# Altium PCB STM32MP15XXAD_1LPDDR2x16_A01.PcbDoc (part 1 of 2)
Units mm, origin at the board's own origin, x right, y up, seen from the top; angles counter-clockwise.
Board outline 86 x 120 mm, 4 copper layers (Top Layer, Signal Layer 1, Signal Layer 2, Bottom Layer), stack 1.571 mm thick; 88 components, 79 nets, 759 pads, 355 vias.
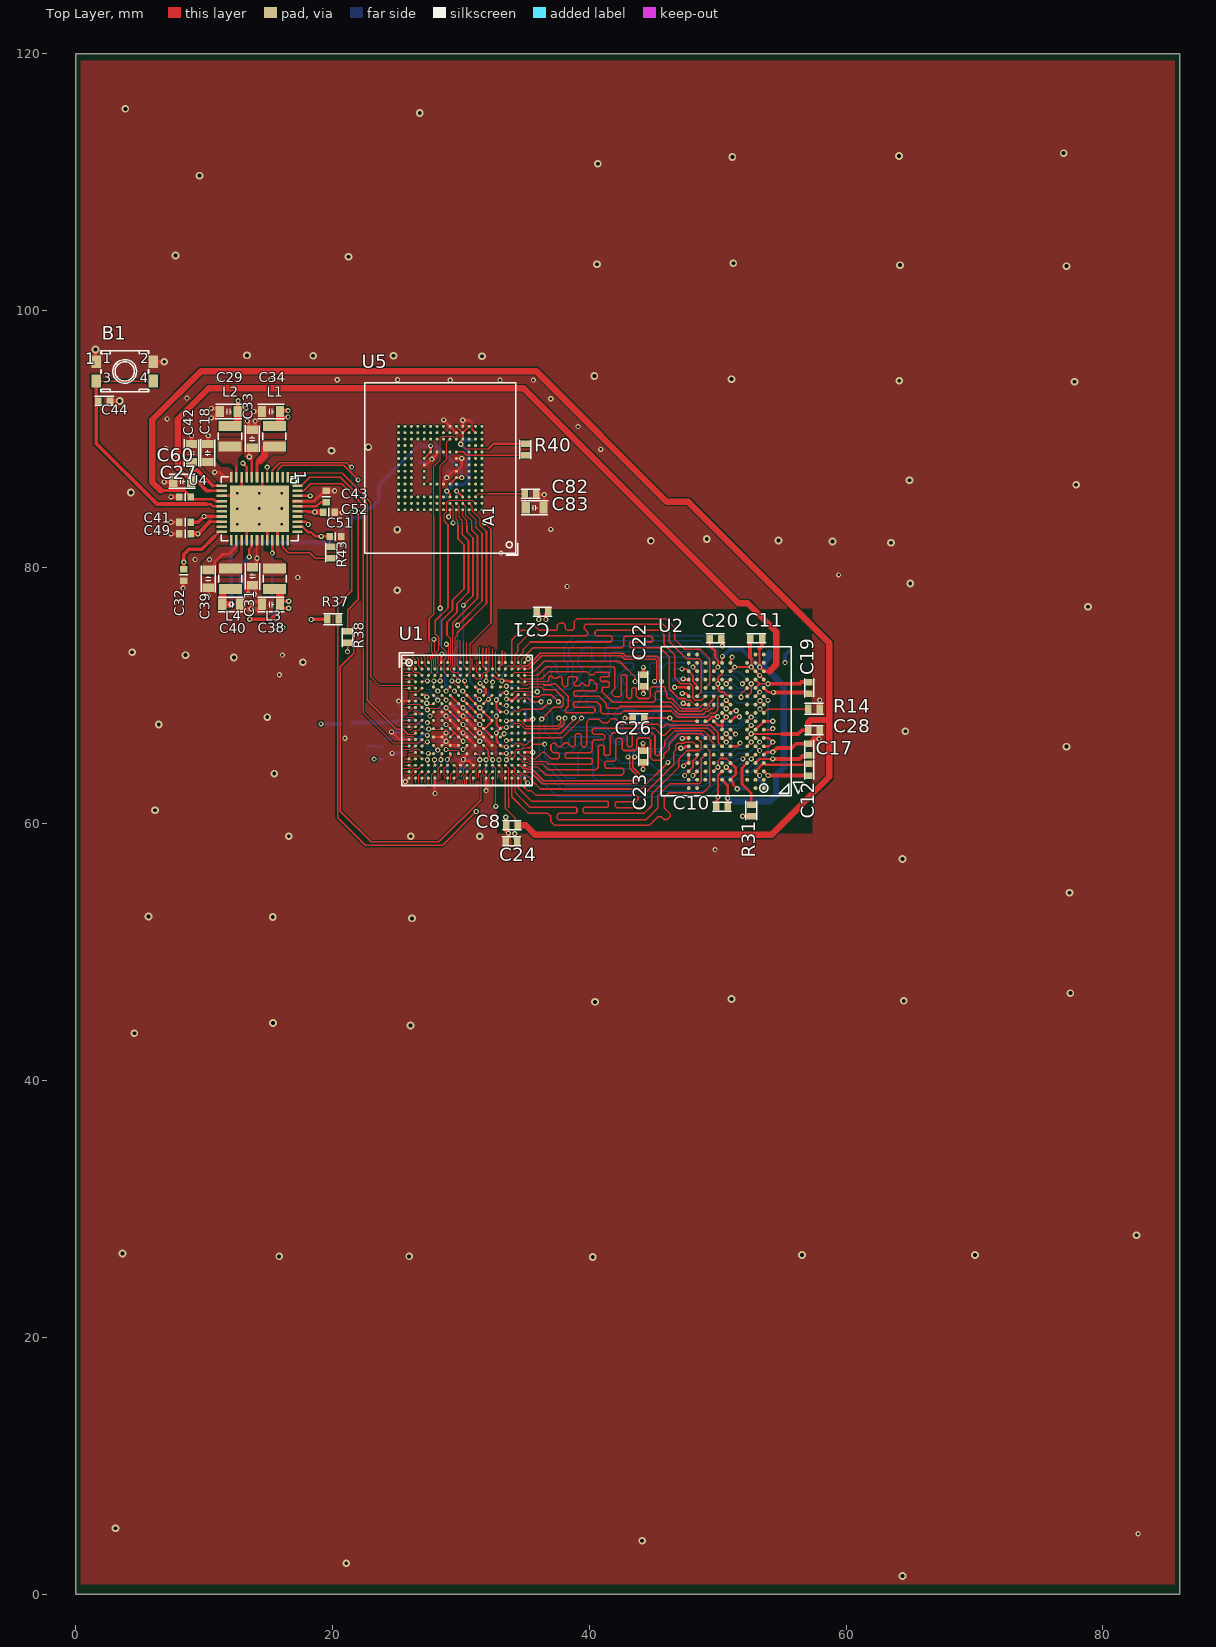
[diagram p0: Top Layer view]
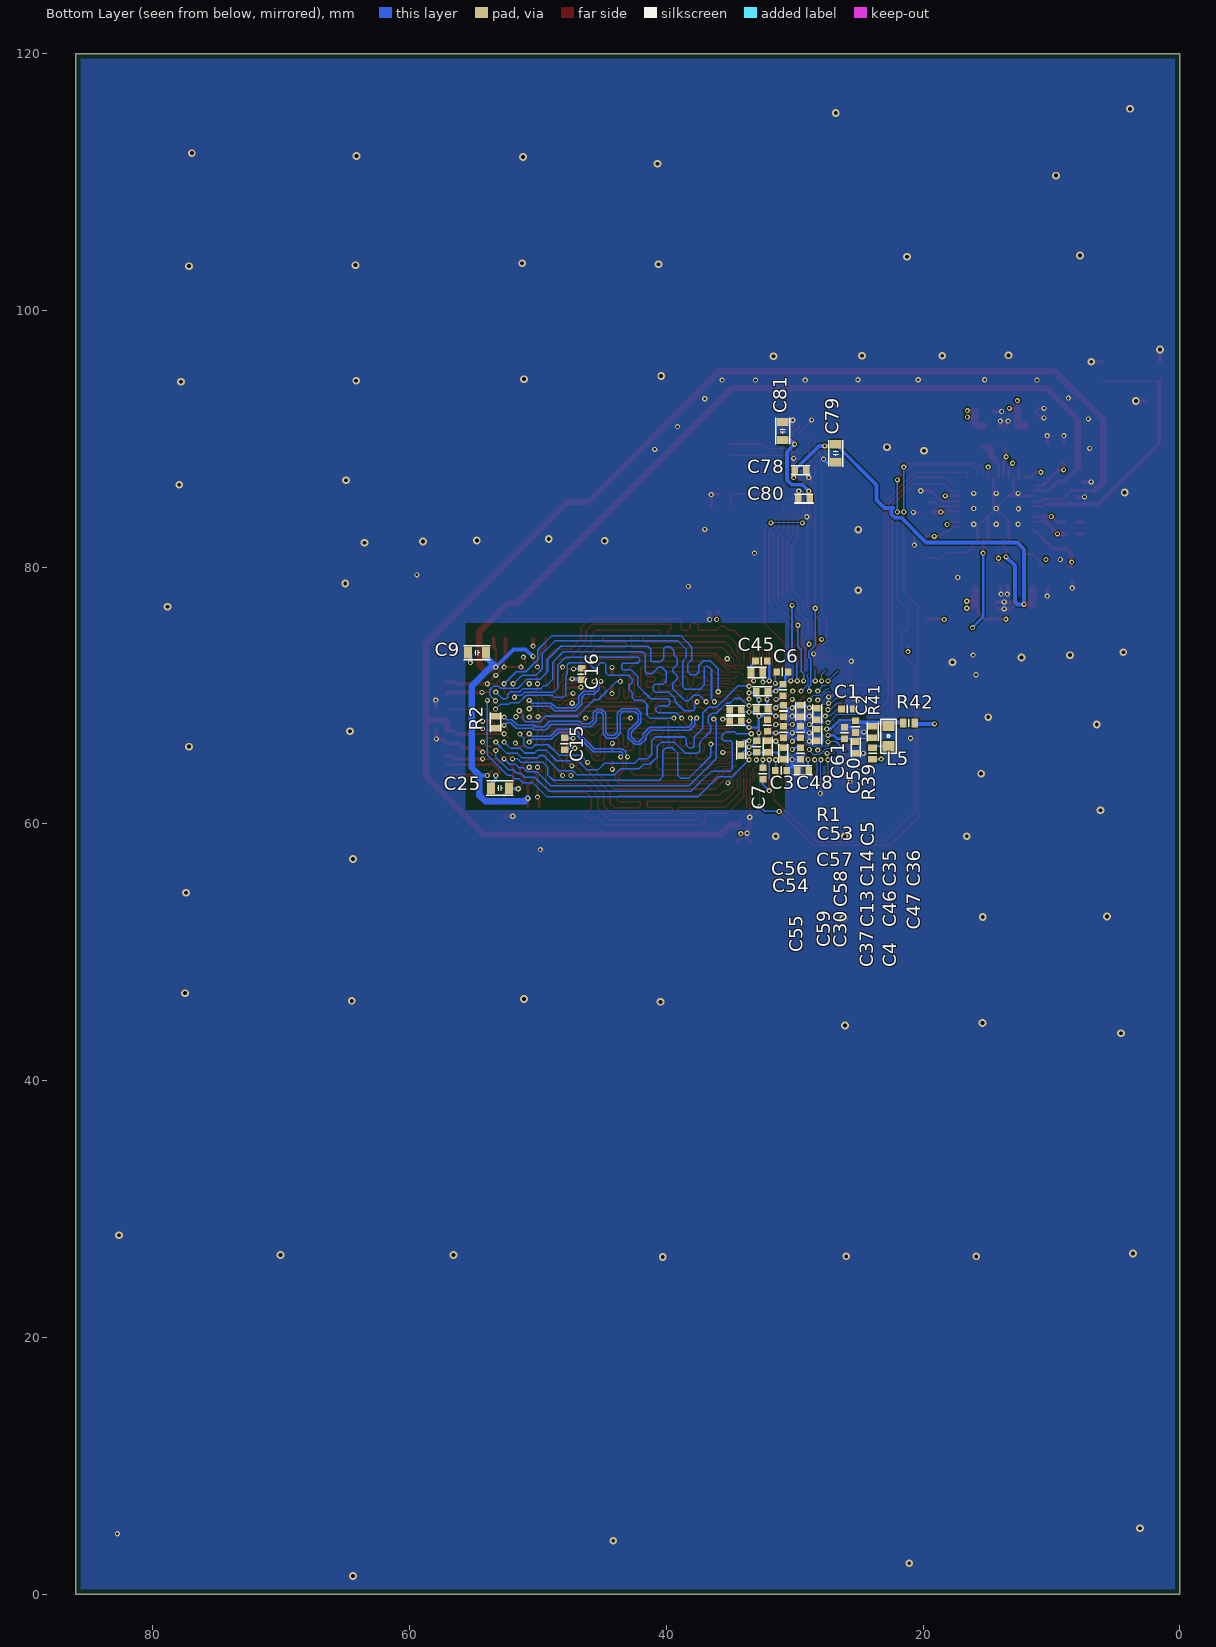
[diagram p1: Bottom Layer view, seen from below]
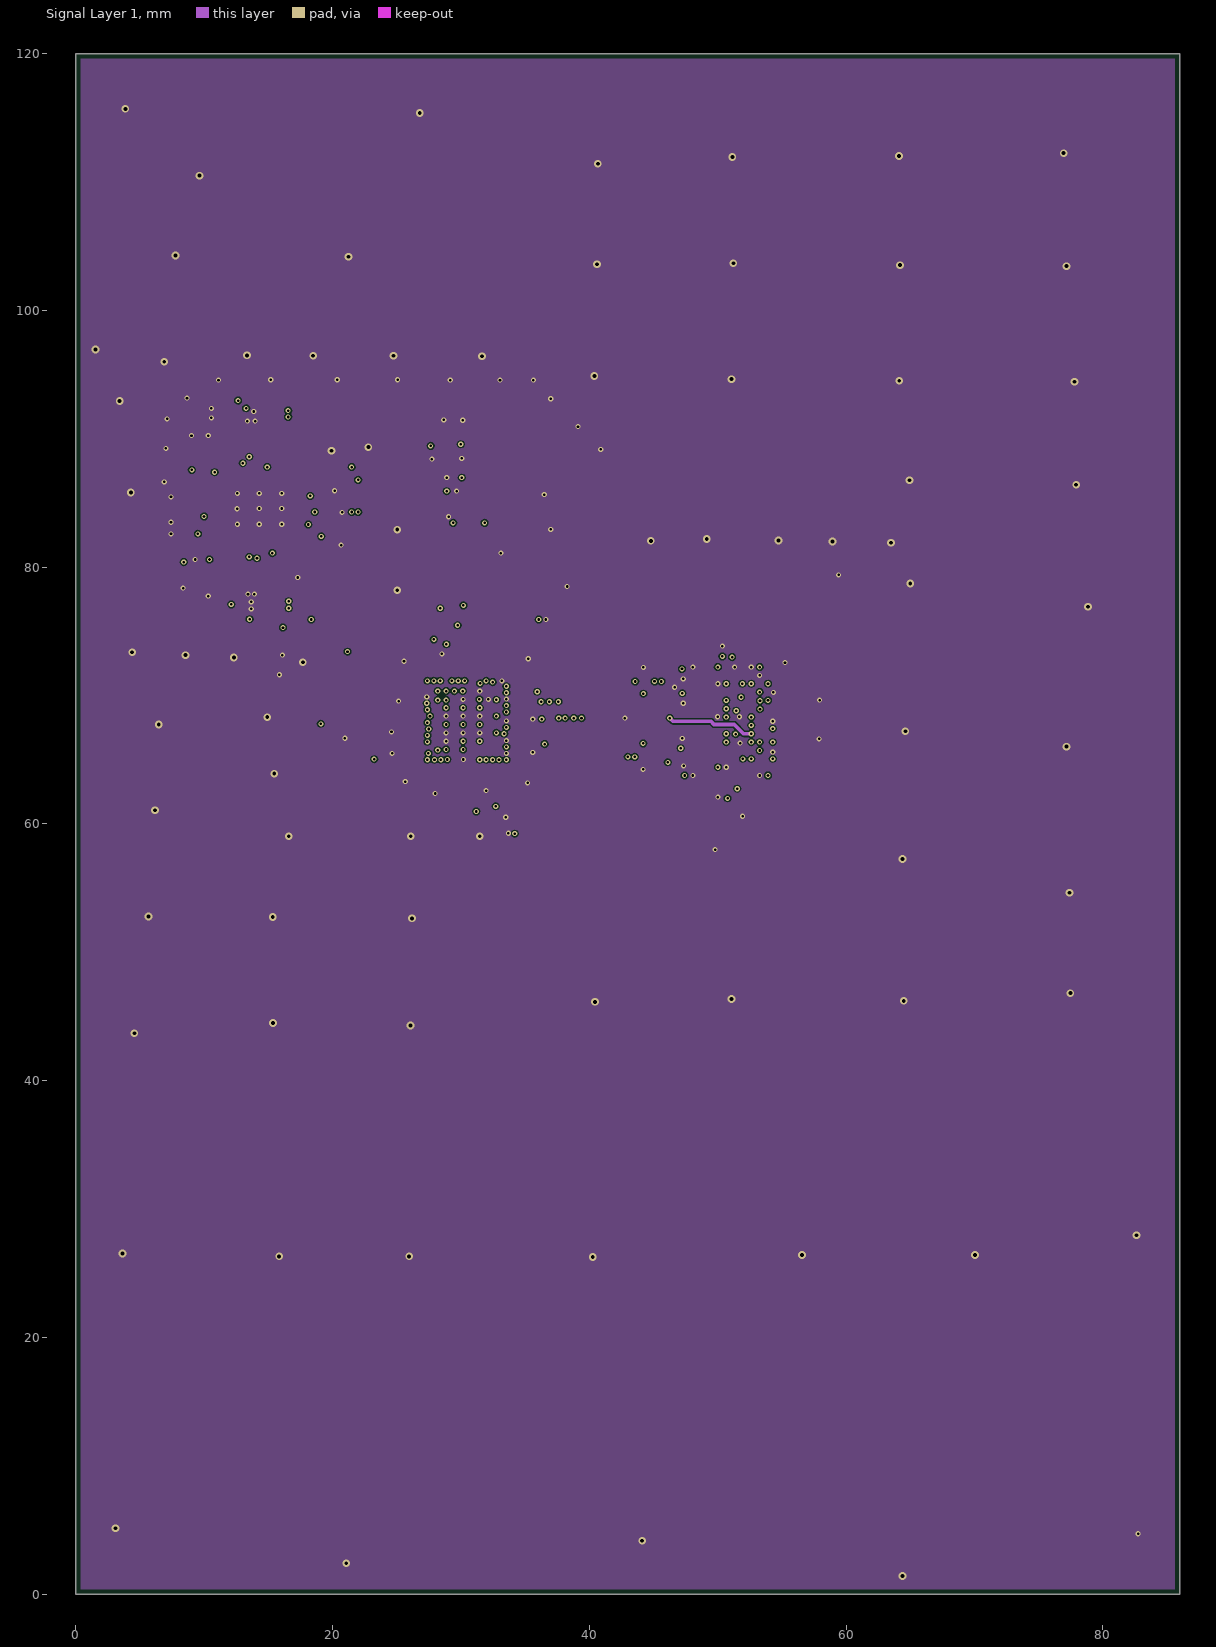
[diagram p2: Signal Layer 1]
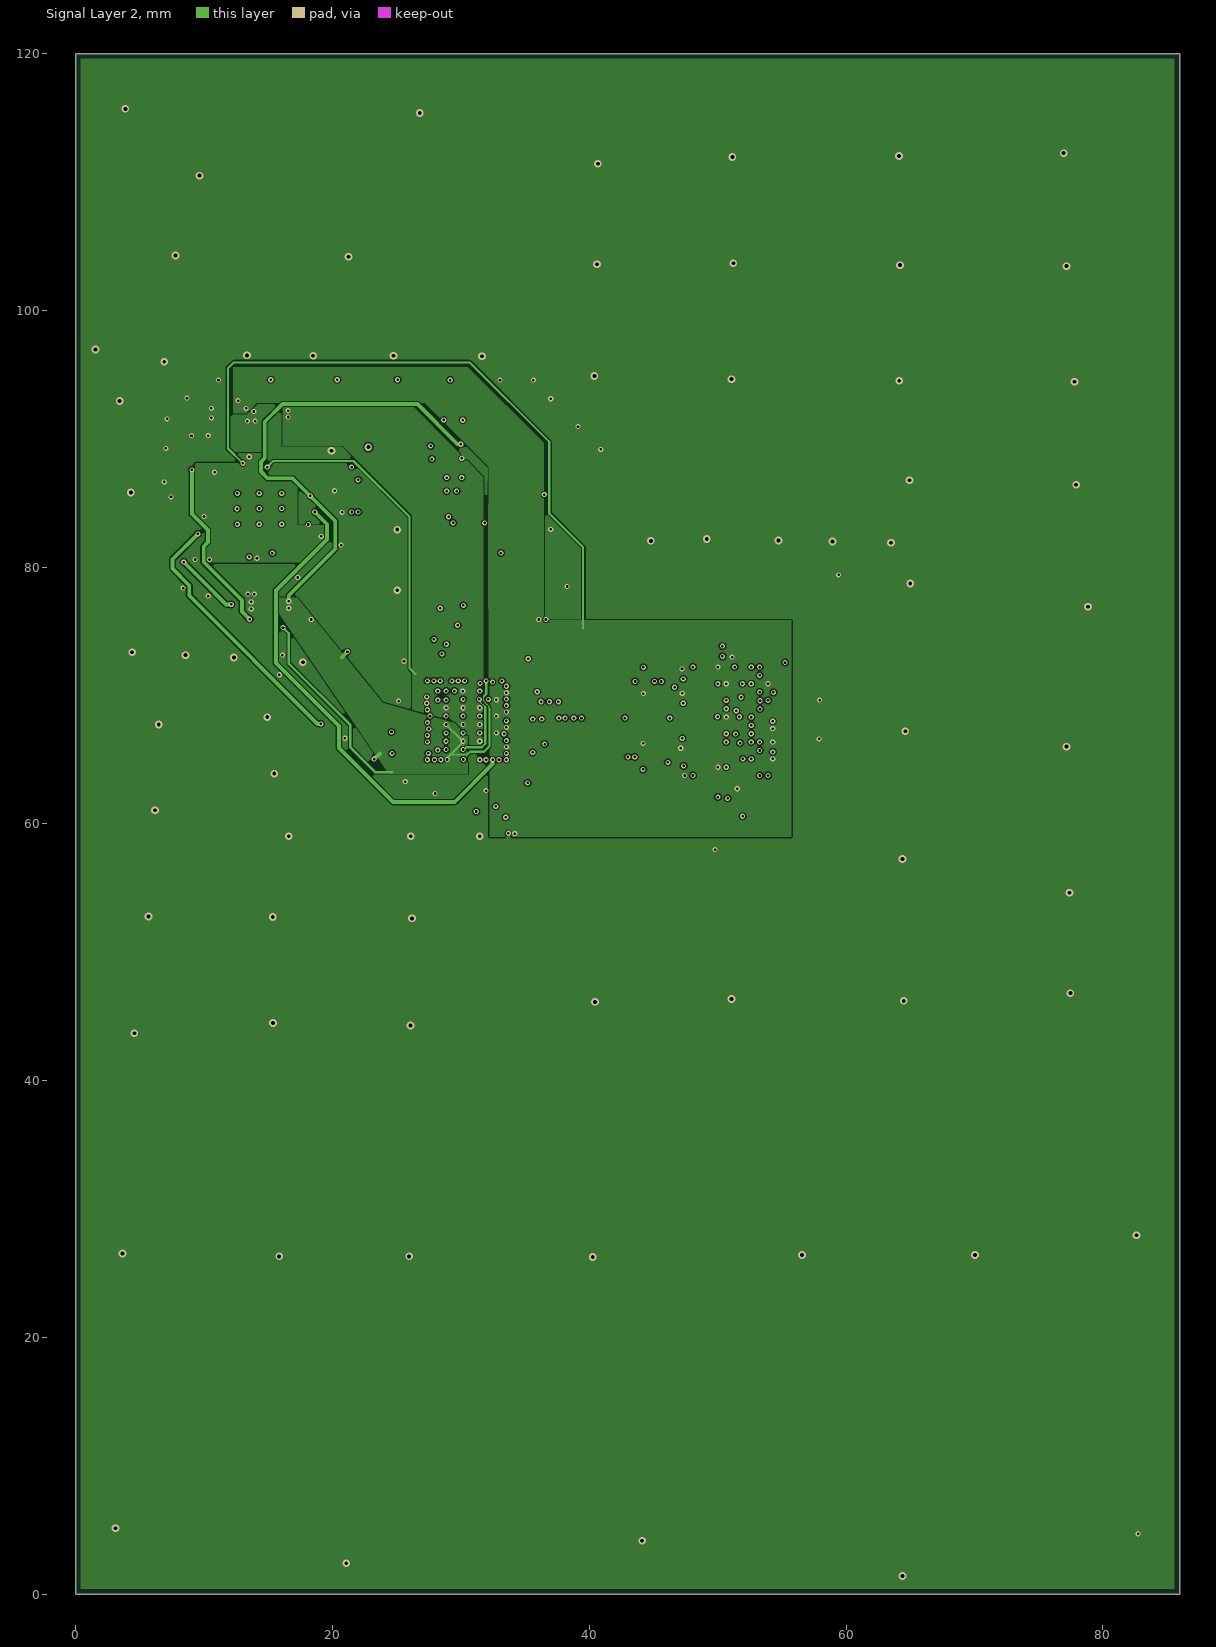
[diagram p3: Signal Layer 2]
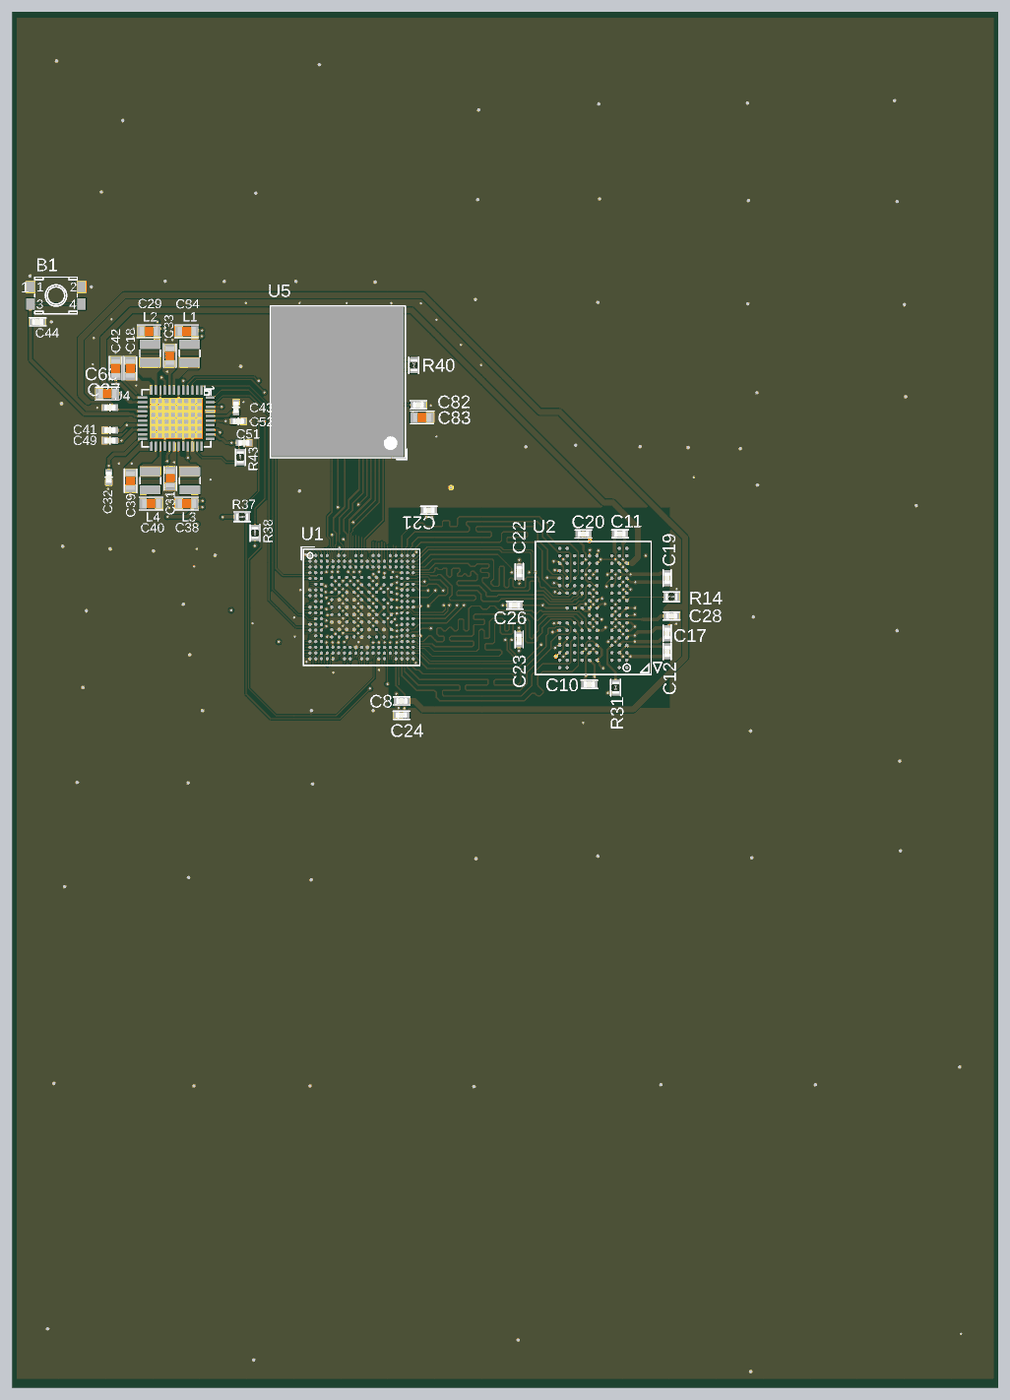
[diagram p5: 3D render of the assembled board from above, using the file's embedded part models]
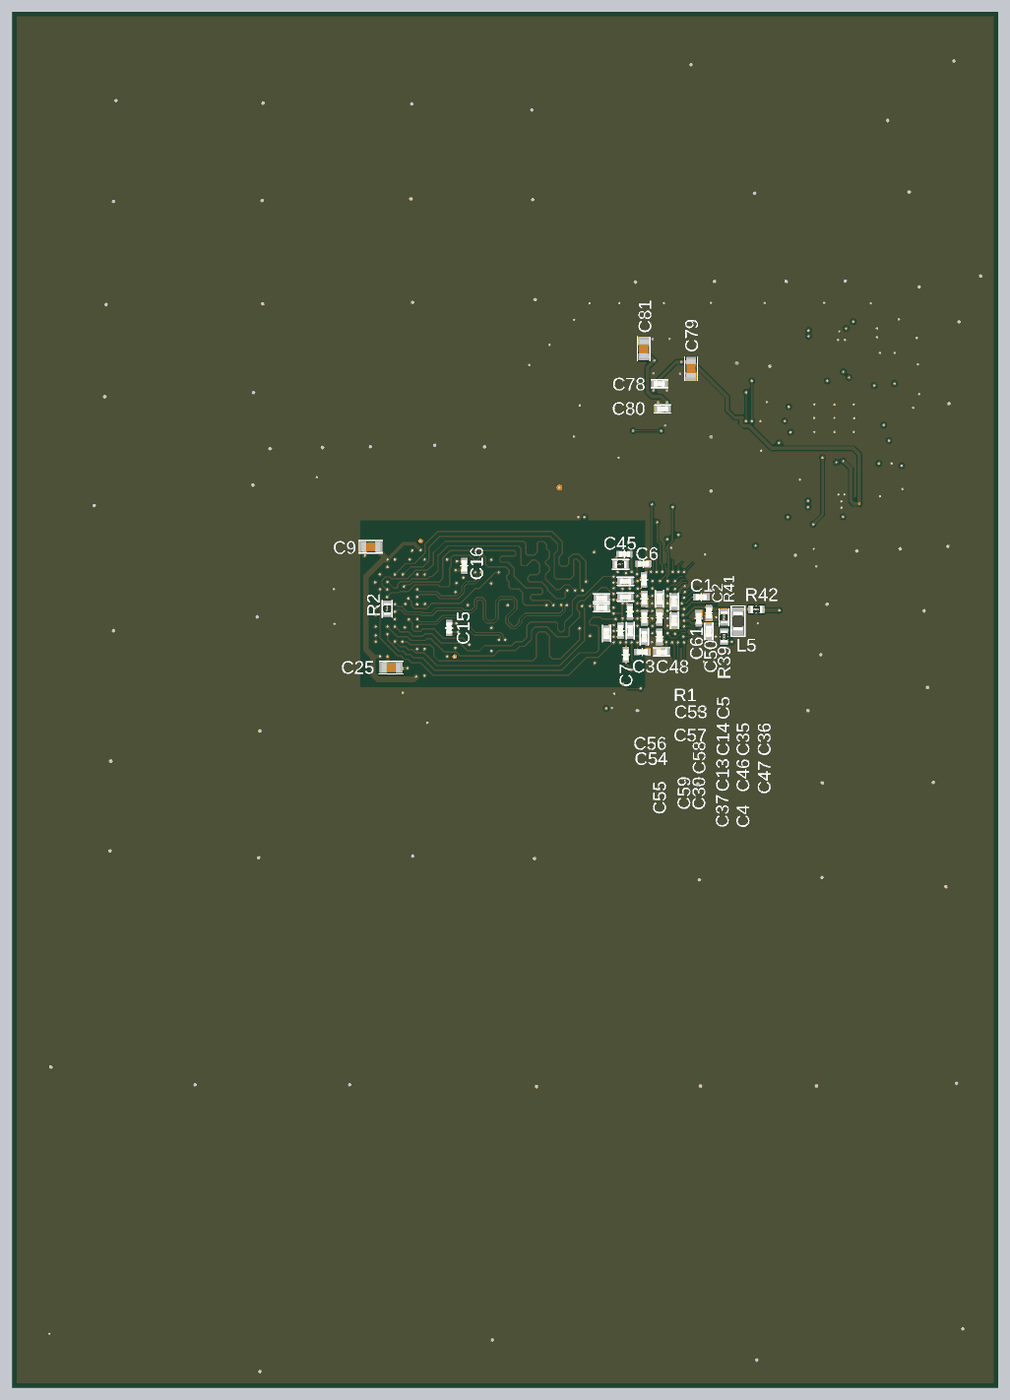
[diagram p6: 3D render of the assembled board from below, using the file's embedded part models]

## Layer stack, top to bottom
Top Solder: solder mask 0.0203, Solder Resist, Dk 3.5
Top Layer: signal copper 0.037
Dielectric 1: core 0.0986, FR-4, Dk 4.1
Signal Layer 1: signal copper 0.035
Dielectric 2: prepreg 1.23, Dk 4.25
Signal Layer 2: signal copper 0.035
Dielectric 3: core 0.0986, Dk 4.1
Bottom Layer: signal copper 0.037
Bottom Solder: solder mask 0.0203, Solder Resist, Dk 3.5

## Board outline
0,0 0,120 86,120 86,0

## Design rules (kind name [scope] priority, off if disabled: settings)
BoardOutlineClearance [All] p1: gap=0.4 ignorepadtopadclearanceinfootprint=FALSE
Clearance diff [InNetClass('diff')] p1: gap=0.1 ignorepadtopadclearanceinfootprint=FALSE except(0: Arc-Hole Track-Hole SMDPad-Hole THPad-Hole Via-Hole Fill-Hole Poly-Hole Region-Hole Text-Hole; 0.08: Track-SMDPad; 0.13: Track-Track; 0.15: Arc-Fill Track-Fill SMDPad-Fill THPad-Fill Via-Fill Fill-Fill; 0.2: Arc-THPad SMDPad-SMDPad SMDPad-THPad THPad-THPad)
Clearance [InNetClass('All Nets')] p2: gap=0.1 ignorepadtopadclearanceinfootprint=FALSE except(0: Arc-Hole Track-Hole SMDPad-Hole THPad-Hole Via-Hole Fill-Hole Poly-Hole Region-Hole Text-Hole; 0.08: Track-Track Track-SMDPad; 0.15: Arc-Fill Track-Fill SMDPad-Fill THPad-Fill Via-Fill Fill-Fill)
ComponentClearance [All] p1 off: gap=0.025 collisioncheckmode=3 verticalgap=2540 showdistances=TRUE
DiffPairsRouting [All] p1: maxlimit=0.13 minlimit=0.13 mostfreqgap=0.13 toplayer_minwidth=0.09 toplayer_maxwidth=0.1 toplayer_prefwidth=0.1 midlayer1_minwidth=0.09 midlayer1_maxwidth=0.1 midlayer1_prefwidth=0.1 midlayer2_minwidth=0.09 midlayer2_maxwidth=0.1 midlayer2_prefwidth=0.1 bottomlayer_minwidth=0.09 bottomlayer_maxwidth=0.1 bottomlayer_prefwidth=0.1 maxuncoupledlength=0.5
FanoutControl Fanout_BGA [IsBGA] p1: bgadir=Out bgaviamode=Closest fanoutstyle=Auto fanoutdirection=Alternating viagrid=0.025 // Fanout_BGA (Default Rule)
FanoutControl Fanout_LCC [IsLCC] p2: bgadir=Out bgaviamode=Closest fanoutstyle=Auto fanoutdirection=Alternating viagrid=0.025 // Fanout_LCC (Default Rule)
FanoutControl Fanout_SOIC [IsSOIC] p3: bgadir=Out bgaviamode=Closest fanoutstyle=Auto fanoutdirection=Alternating viagrid=0.025 // Fanout_SOIC (Default Rule)
FanoutControl Fanout_Small [(CompPinCount < 5)] p4: bgadir=Out bgaviamode=Closest fanoutstyle=Auto fanoutdirection=OutThenIn viagrid=0.025 // Fanout_Small (Default Rule)
FanoutControl Fanout_Default [All] p5: bgadir=Out bgaviamode=Closest fanoutstyle=Auto fanoutdirection=Alternating viagrid=0.025 // Fanout_Default (Default Rule)
Height [All] p1 off: minheight=0 maxheight=100 prefheight=0.5
HoleSize [All] p1: absolutevalues=TRUE maxlimit=10 minlimit=0.15 maxpercent=80.000 minpercent=20.000
HoleToHoleClearance [All] p1: gap=0.25 allowstackedmicrovias=TRUE
Length Length_SDMMC1 [InNetClass('NETC_SDMMC1')] p1: maxlimit=86 minlimit=81
MatchedLengths [All] p1: tolerance=25.4 checknetsindiffpair=FALSE checkdiffpairvsdiffpair=TRUE checkxsignals=TRUE checkothers=TRUE
MinimumSolderMaskSliver [All] p1: minsoldermaskwidth=0
PlaneClearance [All] p1: clearance=0.6
PlaneConnect [All] p1: planeconnectstyle=Direct reliefexpansion=0.508 reliefentries=4 reliefconductorwidth=0.254 reliefairgap=0.254
PolygonConnect [All] p1: connectstyle=Direct reliefconductorwidth=0.254 reliefentries=4 polygonreliefangle="90 Angle" airgapwidth=0.254
RoomDefinition U_STM32_MPU_IOs [InComponentClass('U_STM32_MPU_IOs')] p1 off: confinementstyle=ConfineIn formatcopy=TRUE lockcomponents=FALSE outline 111.75,-5 162.55,-5 162.55,20.4 111.75,20.4
RoomDefinition U_Power_PMIC [InComponentClass('U_Power_PMIC')] p2 off: confinementstyle=ConfineIn formatcopy=TRUE lockcomponents=FALSE outline 105.25,-5.025 156.05,-5.025 156.05,20.375 105.25,20.375
RoomDefinition U_Power_MPU [InComponentClass('U_Power_MPU')] p3 off: confinementstyle=ConfineIn formatcopy=TRUE lockcomponents=FALSE outline 87.122,1.441 142.8,1.441 142.8,7.441 87.122,7.441
RoomDefinition U_LPDDR2_16bits [InComponentClass('U_LPDDR2_16bits')] p4 off: confinementstyle=ConfineIn formatcopy=TRUE lockcomponents=FALSE outline 108.025,-6.875 158.825,-6.875 158.825,18.525 108.025,18.525
RoomDefinition U_eMMC [InComponentClass('U_eMMC')] p5 off: confinementstyle=ConfineIn formatcopy=TRUE lockcomponents=FALSE outline 103.4,-7.825 154.2,-7.825 154.2,17.575 103.4,17.575
RoutingVias RoutingVias_GND [InNetClass('GND')] p1: holewidth=0.3 width=0.6 viastyle="Through Hole" minholewidth=0.2 minwidth=0.4 maxholewidth=0.3 maxwidth=0.6
RoutingVias RoutingVias_ALIMS [InNetClass('ALIMS')] p2: holewidth=0.3 width=0.6 viastyle="Through Hole" minholewidth=0.2 minwidth=0.4 maxholewidth=0.3 maxwidth=0.6
RoutingVias [All] p3: holewidth=0.2 width=0.4 viastyle="Through Hole" minholewidth=0.2 minwidth=0.4 maxholewidth=0.3 maxwidth=0.6
SilkToSilkClearance [All] p1: silktosilkclearance=0
SilkToSolderMaskClearance [IsPad] p1: minsilkscreentomaskgap=0 clearancetoexposedcopper=TRUE
SolderMaskExpansion [All] p1: expansion=0.05
Width VDD_DDR [InNet('VDD_DDR')] p1: maxlimit=0.5 minlimit=0.1 preferedwidth=0.175 minimp=50.000000 maximp=50.000000 favimp=50.000000
Width Width_VCORE [InNet('VDD_CORE')] p2: maxlimit=0.2 minlimit=0.175 preferedwidth=0.175
Width Width_gnd [InNet('GND')] p3: maxlimit=0.5 minlimit=0.1 preferedwidth=0.175 minimp=50.000000 maximp=50.000000 favimp=50.000000
Width [All] p4: maxlimit=0.5 minlimit=0.09 preferedwidth=0.175 toplayer_prefwidth=0.12 bottomlayer_prefwidth=0.12 minimp=50.000000 maximp=50.000000 favimp=50.000000
15 further rules are at their usual default settings.

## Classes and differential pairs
differential pair class DIFF_CLK: DDR_CLK
differential pair class DIFF_DQS1: DDR_DQS1
differential pair class DIFF_DQS0: DDR_DQS0
polygon class POLY_DIRECT_ALL: NETC906_2_L01_P192
component class U_LPDDR2_16bits: C9 C10 C11 C12 C15 C16 C17 C19 C20 C21 C22 C23 C24 C25 C26 C28 R2 R14 R31 U2
component class U_Power_MPU: C1 C2 C3 C4 C5 C6 C7 C13 C14 C30 C35 C36 C37 C45 C46 C47 C48 C50 C53 C54 C55 C56 C57 C58 C59 C61 L5 R39 R41 R42
component class U_Power_PMIC: B1 C18 C27 C29 C31 C32 C33 C34 C38 C39 C40 C41 C42 C43 C44 C49 C51 C52 C60 L1 L2 L3 L4 R43 U4
component class U_eMMC: C78 C79 C80 C81 C82 C83 R40 U5
component class U_STM32_MPU_IOs: C8 R1 R37 R38 U1
net class eMMC_SDIO2_D[0..7]: eMMC_SDIO2_D0 eMMC_SDIO2_D1 eMMC_SDIO2_D2 eMMC_SDIO2_D3 eMMC_SDIO2_D4 eMMC_SDIO2_D5 eMMC_SDIO2_D6 eMMC_SDIO2_D7
differential pair DDR_CLK: +DDR_CLK_P -DDR_CLK_N
differential pair DDR_DQS0: +DDR_DQS0_P -DDR_DQS0_N
differential pair DDR_DQS1: +DDR_DQS1_P -DDR_DQS1_N

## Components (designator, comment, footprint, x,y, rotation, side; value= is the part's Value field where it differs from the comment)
B1 "" SWI_JIUBABA_C-TS-02H-2-5-B-V-T_R_BLUE 3.825,95.25 r0 top value=SW-PUSH-TS-02H-Blue
C1 "" C0402 25.9,68.95 r0 bottom value=100nF
C2 "" C0402 25.25,67.575 r90 bottom value=1uF
C3 "" C0402 31.05,64.175 r0 bottom value=2.2uF
C4 "" C0402 29.55,65.5 r90 bottom value=100nF
C5 "" C0402 30.9,70.45 r270 bottom value=2.2uF
C6 "" C0402 30.95,71.85 r0 bottom value=2.2uF
C7 "" C0402 32.475,63.925 r90 bottom value=100nF
C8 "" C0402 33.975,59.9 r0 top value=100nF
C9 "" C0603 54.73,73.335 r180 bottom value=10uF
C10 "" C0402 50.33,61.35 r180 top value=100nF
C11 "" C0402 53.01,74.47 r180 top value=100nF
C12 "" C0402 57.125,64.225 r90 top value=100nF
C13 "" C0402 30.875,67.15 r90 bottom value=1uF
C14 "" C0402 30.875,68.8 r90 bottom value=1uF
C15 "" C0402 47.9,66.25 r90 bottom value=100nF
C16 "" C0402 46.575,71.675 r270 bottom value=100nF
C17 "" C0402 57.125,65.8 r90 top value=100nF
C18 "" C0603 10.3,88.9 r270 top value=10uF
C19 "" C0402 57.125,70.6 r270 top value=100nF
C20 "" C0402 49.825,74.45 r0 top value=100nF
C21 "" C0402 36.35,76.525 r0 top value=100nF
C22 "" C0402 44.225,71.175 r90 top value=100nF
C23 "" C0402 44.215,65.26 r270 top value=100nF
C24 "" C0402 33.95,58.65 r180 top value=100nF
C25 "" C0603 52.95,62.8 r180 bottom value=10uF
C26 "" C0402 43.825,68.25 r180 top value=100nF
C27 "" C0402 8.525,85.475 r0 top value=1uF
C28 "" C0402 57.5,67.3 r0 top value=100nF
C29 "" C0603 11.925,92.125 r0 top value=22uF
C30 "" C0402 32.1,66.025 r90 bottom value=1uF
C31 "" C0603 13.775,79.3 r90 top value=10uF
C32 "" C0402 8.425,79.4 r90 top value=1uF
C33 "" C0603 13.75,90 r270 top value=10uF
C34 "" C0603 15.225,92.125 r0 top value=22uF
C35 "" C0402 29.55,68.8 r90 bottom value=1uF
C36 "" C0402 28.25,68.575 r90 bottom value=1uF
C37 "" C0402 30.875,65.5 r90 bottom value=1uF
C38 "" C0603 15.225,77.1 r0 top value=22uF
C39 "" C0603 10.325,79.1 r90 top value=10uF
C40 "" C0603 12.125,77.1 r180 top value=22uF
C41 "" C0402 8.525,83.5 r0 top value=1uF
C42 "" C0603 9.025,88.9 r270 top value=10uF
C43 "" C0402 19.525,85.5 r270 top value=4.7uF
C44 "" C0402 2.225,92.95 r180 top value=10nF
C45 "" C0402 32.6,72.7 r180 bottom value=1uF
C46 "" C0402 29.55,67.15 r270 bottom value=1uF
C47 "" C0402 28.25,66.925 r90 bottom value=1uF
C48 "" C0402 29.35,64.175 r180 bottom value=1uF
C49 "" C0402 8.525,82.6 r0 top value=4.7uF
C50 "" C0402 25.25,65.975 r90 bottom value=1uF
C51 "" C0402 20.225,82.4 r0 top value=4.7uF
C52 "" C0402 19.725,84.275 r180 top value=4.7uF
C53 "" C0402 32.525,70.325 r0 bottom value=1uF
C54 "" C0402 34.6,68.025 r180 bottom value=1uF
C55 "" C0402 34.175,65.775 r270 bottom value=3.3nF
C56 "" C0402 34.6,68.875 r180 bottom value=3.3nF
C57 "" C0402 32.525,68.95 r0 bottom value=3.3nF
C58 "" C0402 32.125,67.675 r90 bottom value=1nF
C59 "" C0402 32.95,66.025 r90 bottom value=1nF
C60 "" C0603 8.3,86.7 r0 top value=10uF
C61 "" C0402 26.125,67.1 r270 bottom value=10nF
C78 "" C0402 29.55,87.55 r0 bottom value=100nF
C79 "" C0603 26.8,88.875 r90 bottom value=2.2uF
C80 "" C0402 29.275,85.35 r180 bottom value=100nF
C81 "" C0603 30.925,90.6 r270 bottom value=2.2uF
C82 "" C0402 35.425,85.725 r180 top value=100nF
C83 "" C0603 35.75,84.625 r180 top value=2.2uF
L1 "" IND_MURATA_DFE201612P 15.475,90.2 r90 top value=DFE201612P-1R0M
L2 "" IND_MURATA_DFE201612P 12.025,90.2 r90 top value=DFE201612P-1R0M
L3 "" IND_MURATA_DFE201612P 15.5,79.1 r270 top value=DFE201612P-1R0M
L4 "" IND_MURATA_DFE201612P 12.05,79.1 r270 top value=DFE201612P-1R0M
L5 "" L0603_H0P8 22.7,66.85 r90 bottom value=LQM18FN4R7M00D
R1 "" R0402 32.95,71.8 r0 bottom value="240R 1%"
R2 "" R0402 53.3,67.925 r270 bottom value=100R
R14 "" R0402 57.5,68.975 r180 top value=10K
R31 "" R0402 52.625,61.05 r270 top value="240R 1%"
R37 "" R0402 20.05,75.95 r0 top value=1K5
R38 "" R0402 21.175,74.55 r90 top value=1K5
R39 "" R0402 23.925,65.5 r90 bottom value=0R
R40 "" R0402 35.025,89.175 r90 top value=10K
R41 "" R0402 23.925,67.175 r270 bottom value=0R
R42 "" R0402 21.1,67.875 r0 bottom value=0R
R43 "" R0402 19.9,81.15 r90 top value=47K
U1 "" ICC_TFBGA257_10X10_STM32MP157CAD3_P050-065 30.475,68.075 r0 top value=STM32MP157CAD3
U2 "" ICC_WFBGA134_SDP-SAC302_10X11P5_P065 50.675,68 r180 top locked value=EDB4432BBBJ-1D-F-R
U4 "" ICC_WFQFN44-EPAD_5X6_P040 14.325,84.55 r270 top value=STPMIC1APQR
U5 "" ICC_P-WFBGA153_13X11P5_P050 28.4,87.725 r90 top locked value=THGBMDG5D1LBAIL

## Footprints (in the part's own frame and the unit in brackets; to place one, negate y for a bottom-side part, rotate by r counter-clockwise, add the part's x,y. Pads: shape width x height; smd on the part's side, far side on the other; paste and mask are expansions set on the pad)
C0402 [mm]
  rect 0.51x0.56 smd mask+0.05: 1(-0.45,0) 2(0.45,0)
  silkscreen extent 0,-0.3 0,0.3, body extent -0.5,-0.3 0.5,0.3, height 0.4
C0603 [mm]
  rect 0.64x0.89 smd mask+0.05: 1(-0.7,0) 2(0.7,0)
  silkscreen extent -1.05,-0.55 1.02,0.55, body extent -0.9,-0.5 0.9,0.5, height 1.4
ICC_P-WFBGA153_13X11P5_P050 [mm]
  round 0.23 smd mask+0.05: A1(-3.25,-3.25) A2(-3.25,-2.75) A3(-3.25,-2.25) A4(-3.25,-1.75) A5(-3.25,-1.25) A6(-3.25,-0.75) A7(-3.25,-0.25) A8(-3.25,0.25) A9(-3.25,0.75) A10(-3.25,1.25) A11(-3.25,1.75) A12(-3.25,2.25) A13(-3.25,2.75) A14(-3.25,3.25) B1(-2.75,-3.25) B2(-2.75,-2.75) B3(-2.75,-2.25) B4(-2.75,-1.75) B5(-2.75,-1.25) B6(-2.75,-0.75) B7(-2.75,-0.25) B8(-2.75,0.25) B9(-2.75,0.75) B10(-2.75,1.25) B11(-2.75,1.75) B12(-2.75,2.25) B13(-2.75,2.75) B14(-2.75,3.25) C1(-2.25,-3.25) C2(-2.25,-2.75) C3(-2.25,-2.25) C4(-2.25,-1.75) C5(-2.25,-1.25) C6(-2.25,-0.75) C7(-2.25,-0.25) C8(-2.25,0.25) C9(-2.25,0.75) C10(-2.25,1.25) C11(-2.25,1.75) C12(-2.25,2.25) C13(-2.25,2.75) C14(-2.25,3.25) D1(-1.75,-3.25) D2(-1.75,-2.75) D3(-1.75,-2.25) D4(-1.75,-1.75) D12(-1.75,2.25) D13(-1.75,2.75) D14(-1.75,3.25) E1(-1.25,-3.25) E2(-1.25,-2.75) E3(-1.25,-2.25) E5(-1.25,-1.25) E6(-1.25,-0.75) E7(-1.25,-0.25) E8(-1.25,0.25) E9(-1.25,0.75) E10(-1.25,1.25) E12(-1.25,2.25) E13(-1.25,2.75) E14(-1.25,3.25) F1(-0.75,-3.25) F2(-0.75,-2.75) F3(-0.75,-2.25) F5(-0.75,-1.25) F10(-0.75,1.25) F12(-0.75,2.25) F13(-0.75,2.75) F14(-0.75,3.25) G1(-0.25,-3.25) G2(-0.25,-2.75) G3(-0.25,-2.25) G5(-0.25,-1.25) G10(-0.25,1.25) G12(-0.25,2.25) G13(-0.25,2.75) G14(-0.25,3.25) H1(0.25,-3.25) H2(0.25,-2.75) H3(0.25,-2.25) H5(0.25,-1.25) H10(0.25,1.25) H12(0.25,2.25) H13(0.25,2.75) H14(0.25,3.25) J1(0.75,-3.25) J2(0.75,-2.75) J3(0.75,-2.25) J5(0.75,-1.25) J10(0.75,1.25) J12(0.75,2.25) J13(0.75,2.75) J14(0.75,3.25) K1(1.25,-3.25) K2(1.25,-2.75) K3(1.25,-2.25) K5(1.25,-1.25) K6(1.25,-0.75) K7(1.25,-0.25) K8(1.25,0.25) K9(1.25,0.75) K10(1.25,1.25) K12(1.25,2.25) K13(1.25,2.75) K14(1.25,3.25) L1(1.75,-3.25) L2(1.75,-2.75) L3(1.75,-2.25) L12(1.75,2.25) L13(1.75,2.75) L14(1.75,3.25) M1(2.25,-3.25) M2(2.25,-2.75) M3(2.25,-2.25) M4(2.25,-1.75) M5(2.25,-1.25) M6(2.25,-0.75) M7(2.25,-0.25) M8(2.25,0.25) M9(2.25,0.75) M10(2.25,1.25) M11(2.25,1.75) M12(2.25,2.25) M13(2.25,2.75) M14(2.25,3.25) N1(2.75,-3.25) N2(2.75,-2.75) N3(2.75,-2.25) N4(2.75,-1.75) N5(2.75,-1.25) N6(2.75,-0.75) N7(2.75,-0.25) N8(2.75,0.25) N9(2.75,0.75) N10(2.75,1.25) N11(2.75,1.75) N12(2.75,2.25) N13(2.75,2.75) N14(2.75,3.25) P1(3.25,-3.25) P2(3.25,-2.75) P3(3.25,-2.25) P4(3.25,-1.75) P5(3.25,-1.25) P6(3.25,-0.75) P7(3.25,-0.25) P8(3.25,0.25) P9(3.25,0.75) P10(3.25,1.25) P11(3.25,1.75) P12(3.25,2.25) P13(3.25,2.75) P14(3.25,3.25)
  silkscreen extent -6.78,-6.02 6.63,5.87, body extent -6.55,-5.8 6.55,5.8, height 1
ICC_TFBGA257_10X10_STM32MP157CAD3_P050-065 [mm] "MCD-01144"
  round 0.23 smd paste+0.025 mask+0.05: 1A1(-2.6,2.6) 1A2(-1.95,2.6) 1A3(-1.3,2.6) 1A4(-0.65,2.6) 1A5(0,2.6) 1A6(0.65,2.6) 1A7(1.3,2.6) 1A8(1.95,2.6) 1A9(2.6,2.6) 1B1(-2.6,1.95) 1B2(-1.95,1.95) 1B3(-1.3,1.95) 1B4(-0.65,1.95) 1B5(0,1.95) 1B6(0.65,1.95) 1B7(1.3,1.95) 1B8(1.95,1.95) 1B9(2.6,1.95) 1C1(-2.6,1.3) 1C2(-1.95,1.3) 1C3(-1.3,1.3) 1C4(-0.65,1.3) 1C5(0,1.3) 1C6(0.65,1.3) 1C7(1.3,1.3) 1C8(1.95,1.3) 1C9(2.6,1.3) 1D1(-2.6,0.65) 1D2(-1.95,0.65) 1D3(-1.3,0.65) 1D4(-0.65,0.65) 1D5(0,0.65) 1D6(0.65,0.65) 1D7(1.3,0.65) 1D8(1.95,0.65) 1D9(2.6,0.65) 1E1(-2.6,0) 1E2(-1.95,0) 1E3(-1.3,0) 1E4(-0.65,0) 1E5(0,0) 1E6(0.65,0) 1E7(1.3,0) 1E8(1.95,0) 1E9(2.6,0) 1F1(-2.6,-0.65) 1F2(-1.95,-0.65) 1F3(-1.3,-0.65) 1F4(-0.65,-0.65) 1F5(0,-0.65) 1F6(0.65,-0.65) 1F7(1.3,-0.65) 1F8(1.95,-0.65) 1F9(2.6,-0.65) 1G1(-2.6,-1.3) 1G2(-1.95,-1.3) 1G3(-1.3,-1.3) 1G4(-0.65,-1.3) 1G5(0,-1.3) 1G6(0.65,-1.3) 1G7(1.3,-1.3) 1G8(1.95,-1.3) 1G9(2.6,-1.3) 1H1(-2.6,-1.95) 1H2(-1.95,-1.95) 1H3(-1.3,-1.95) 1H4(-0.65,-1.95) 1H5(0,-1.95) 1H6(0.65,-1.95) 1H7(1.3,-1.95) 1H8(1.95,-1.95) 1H9(2.6,-1.95) 1J1(-2.6,-2.6) 1J2(-1.95,-2.6) 1J3(-1.3,-2.6) 1J4(-0.65,-2.6) 1J5(0,-2.6) 1J6(0.65,-2.6) 1J7(1.3,-2.6) 1J8(1.95,-2.6) 1J9(2.6,-2.6) A1(-4.5,4.5) A2(-4,4.5) A3(-3.5,4.5) A4(-3,4.5) A6(-2,4.5) A7(-1.5,4.5) A9(-0.5,4.5) A10(0,4.5) A12(1,4.5) A13(1.5,4.5) A15(2.5,4.5) A16(3,4.5) A17(3.5,4.5) A18(4,4.5) A19(4.5,4.5) B1(-4.5,4) B2(-4,4) B3(-3.5,4) B4(-3,4) B5(-2.5,4) B6(-2,4) B7(-1.5,4) B8(-1,4) B9(-0.5,4) B10(0,4) B11(0.5,4) B12(1,4) B13(1.5,4) B14(2,4) B15(2.5,4) B16(3,4) B17(3.5,4) B18(4,4) B19(4.5,4) C1(-4.5,3.5) C2(-4,3.5) C3(-3.5,3.5) C4(-3,3.5) C5(-2.5,3.5) C6(-2,3.5) C7(-1.5,3.5) C8(-1,3.5) C9(-0.5,3.5) C10(0,3.5) C11(0.5,3.5) C12(1,3.5) C13(1.5,3.5) C14(2,3.5) C15(2.5,3.5) C16(3,3.5) C17(3.5,3.5) C18(4,3.5) C19(4.5,3.5) D1(-4.5,3) D2(-4,3) D3(-3.5,3) D17(3.5,3) D18(4,3) D19(4.5,3) E1(-4.5,2.5) E2(-4,2.5) E3(-3.5,2.5) E17(3.5,2.5) E18(4,2.5) F2(-4,2) F3(-3.5,2) F17(3.5,2) F18(4,2) F19(4.5,2) G1(-4.5,1.5) G2(-4,1.5) G3(-3.5,1.5) G17(3.5,1.5) G18(4,1.5) G19(4.5,1.5) H1(-4.5,1) H2(-4,1) H3(-3.5,1) H17(3.5,1) H18(4,1) J2(-4,0.5) J3(-3.5,0.5) J17(3.5,0.5) J18(4,0.5) J19(4.5,0.5) K1(-4.5,0) K2(-4,0) K3(-3.5,0) K17(3.5,0) K18(4,0) K19(4.5,0) L1(-4.5,-0.5) L2(-4,-0.5) L3(-3.5,-0.5) L17(3.5,-0.5) L18(4,-0.5) M2(-4,-1) M3(-3.5,-1) M17(3.5,-1) M18(4,-1) M19(4.5,-1) N1(-4.5,-1.5) N2(-4,-1.5) N3(-3.5,-1.5) N17(3.5,-1.5) N18(4,-1.5) N19(4.5,-1.5) P1(-4.5,-2) P2(-4,-2) P3(-3.5,-2) P17(3.5,-2) P18(4,-2) R2(-4,-2.5) R3(-3.5,-2.5) R17(3.5,-2.5) R18(4,-2.5) R19(4.5,-2.5) T1(-4.5,-3) T2(-4,-3) T3(-3.5,-3) T17(3.5,-3) T18(4,-3) T19(4.5,-3) U1(-4.5,-3.5) U2(-4,-3.5) U3(-3.5,-3.5) U4(-3,-3.5) U5(-2.5,-3.5) U6(-2,-3.5) U7(-1.5,-3.5) U8(-1,-3.5) U9(-0.5,-3.5) U10(0,-3.5) U11(0.5,-3.5) U12(1,-3.5) U13(1.5,-3.5) U14(2,-3.5) U15(2.5,-3.5) U16(3,-3.5) U17(3.5,-3.5) U18(4,-3.5) U19(4.5,-3.5) V1(-4.5,-4) V2(-4,-4) V3(-3.5,-4) V4(-3,-4) V5(-2.5,-4) V6(-2,-4) V7(-1.5,-4) V8(-1,-4) V9(-0.5,-4) V10(0,-4) V11(0.5,-4) V12(1,-4) V13(1.5,-4) V14(2,-4) V15(2.5,-4) V16(3,-4) V17(3.5,-4) V18(4,-4) V19(4.5,-4) W1(-4.5,-4.5) W2(-4,-4.5) W3(-3.5,-4.5) W4(-3,-4.5) W5(-2.5,-4.5) W7(-1.5,-4.5) W8(-1,-4.5) W10(0,-4.5) W11(0.5,-4.5) W13(1.5,-4.5) W14(2,-4.5) W16(3,-4.5) W17(3.5,-4.5) W18(4,-4.5) W19(4.5,-4.5)
  silkscreen extent -5.25,-5.07 5.07,5.25, body extent -5.07,-5.07 5.07,5.07, height 1.21
ICC_WFBGA134_SDP-SAC302_10X11P5_P065 [mm] "IPC"
  round 0.3 smd mask+0.05: A1(-2.925,5.2) A2(-2.275,5.2) A9(2.275,5.2) A10(2.925,5.2) B1(-2.925,4.55) B2(-2.275,4.55) B3(-1.625,4.55) B5(-0.325,4.55) B6(0.325,4.55) B7(0.975,4.55) B8(1.625,4.55) B9(2.275,4.55) B10(2.925,4.55) C1(-2.925,3.9) C2(-2.275,3.9) C3(-1.625,3.9) C5(-0.325,3.9) C6(0.325,3.9) C7(0.975,3.9) C8(1.625,3.9) C9(2.275,3.9) C10(2.925,3.9) D1(-2.925,3.25) D2(-2.275,3.25) D3(-1.625,3.25) D5(-0.325,3.25) D6(0.325,3.25) D7(0.975,3.25) D8(1.625,3.25) D9(2.275,3.25) D10(2.925,3.25) E1(-2.925,2.6) E2(-2.275,2.6) E3(-1.625,2.6) E5(-0.325,2.6) E6(0.325,2.6) E7(0.975,2.6) E8(1.625,2.6) E9(2.275,2.6) E10(2.925,2.6) F1(-2.925,1.95) F2(-2.275,1.95) F3(-1.625,1.95) F5(-0.325,1.95) F6(0.325,1.95) F7(0.975,1.95) F8(1.625,1.95) F9(2.275,1.95) F10(2.925,1.95) G1(-2.925,1.3) G2(-2.275,1.3) G3(-1.625,1.3) G5(-0.325,1.3) G6(0.325,1.3) G7(0.975,1.3) G8(1.625,1.3) G9(2.275,1.3) G10(2.925,1.3) H1(-2.925,0.65) H2(-2.275,0.65) H3(-1.625,0.65) H5(-0.325,0.65) H6(0.325,0.65) J1(-2.925,0) J2(-2.275,0) J3(-1.625,0) J5(-0.325,0) J6(0.325,0) J7(0.975,0) J8(1.625,0) J9(2.275,0) K1(-2.925,-0.65) K2(-2.275,-0.65) K3(-1.625,-0.65) K5(-0.325,-0.65) K6(0.325,-0.65) L1(-2.925,-1.3) L2(-2.275,-1.3) L3(-1.625,-1.3) L5(-0.325,-1.3) L6(0.325,-1.3) L7(0.975,-1.3) L8(1.625,-1.3) L9(2.275,-1.3) L10(2.925,-1.3) M1(-2.925,-1.95) M2(-2.275,-1.95) M3(-1.625,-1.95) M5(-0.325,-1.95) M6(0.325,-1.95) M7(0.975,-1.95) M8(1.625,-1.95) M9(2.275,-1.95) M10(2.925,-1.95) N1(-2.925,-2.6) N2(-2.275,-2.6) N3(-1.625,-2.6) N5(-0.325,-2.6) N6(0.325,-2.6) N7(0.975,-2.6) N8(1.625,-2.6) N9(2.275,-2.6) N10(2.925,-2.6) P1(-2.925,-3.25) P2(-2.275,-3.25) P3(-1.625,-3.25) P5(-0.325,-3.25) P6(0.325,-3.25) P7(0.975,-3.25) P8(1.625,-3.25) P9(2.275,-3.25) P10(2.925,-3.25) R1(-2.925,-3.9) R2(-2.275,-3.9) R3(-1.625,-3.9) R5(-0.325,-3.9) R6(0.325,-3.9) R7(0.975,-3.9) R8(1.625,-3.9) R9(2.275,-3.9) R10(2.925,-3.9) T1(-2.925,-4.55) T2(-2.275,-4.55) T3(-1.625,-4.55) T5(-0.325,-4.55) T6(0.325,-4.55) T7(0.975,-4.55) T8(1.625,-4.55) T9(2.275,-4.55) T10(2.925,-4.55) U1(-2.925,-5.2) U2(-2.275,-5.2) U9(2.275,-5.2) U10(2.925,-5.2)
  silkscreen extent -5.97,-5.8 5.05,5.8, body extent -5.05,-5.8 5.05,5.8, height 0.76
ICC_WFQFN44-EPAD_5X6_P040 [mm]
  rect 0.8x0.2 smd mask+0.05: 1(-2.45,2.2) 2(-2.45,1.8) 3(-2.45,1.4) 4(-2.45,1) 5(-2.45,0.6) 6(-2.45,0.2) 7(-2.45,-0.2) 8(-2.45,-0.6) 9(-2.45,-1) 10(-2.45,-1.4) 11(-2.45,-1.8) 12(-2.45,-2.2) 23(2.45,-2.2) 24(2.45,-1.8) 25(2.45,-1.4) 26(2.45,-1) 27(2.45,-0.6) 28(2.45,-0.2) 29(2.45,0.2) 30(2.45,0.6) 31(2.45,1) 32(2.45,1.4) 33(2.45,1.8) 34(2.45,2.2)
  rect 0.2x0.8 smd mask+0.05: 13(-1.8,-2.95) 14(-1.4,-2.95) 15(-1,-2.95) 16(-0.6,-2.95) 17(-0.2,-2.95) 18(0.2,-2.95) 19(0.6,-2.95) 20(1,-2.95) 21(1.4,-2.95) 22(1.8,-2.95) 35(1.8,2.95) 36(1.4,2.95) 37(1,2.95) 38(0.6,2.95) 39(0.2,2.95) 40(-0.2,2.95) 41(-0.6,2.95) 42(-1,2.95) 43(-1.4,2.95) 44(-1.8,2.95)
  rect 3.6x4.6 smd paste-1.8 mask+0.05: ep(0,0)
  silkscreen extent -2.5,-3 2.5,3, body extent -2.5,-3 2.5,3, height 0.81
IND_MURATA_DFE201612P [mm] "MCD-01491"
  rect 0.8x1.8 smd mask+0.05: 1(-0.8,0) 2(0.8,0)
  silkscreen extent -0.28,-0.9 0.28,0.9, body extent -1.1,-0.9 1.1,0.9, height 1.2
L0603_H0P8 [mm]
  rect 0.8x0.95 smd mask+0.05: 1(-0.8,0) 2(0.8,0)
  silkscreen extent -1.33,-0.6 1.33,0.6, body extent -0.87,-0.47 0.87,0.47, height 0.9
R0402 [mm]
  rect 0.51x0.7 smd mask+0.05: 1(-0.45,0) 2(0.45,0)
  silkscreen extent -0.72,-0.43 0.72,0.43, body extent -0.52,-0.3 0.52,0.3, height 0.4
SWI_JIUBABA_C-TS-02H-2-5-B-V-T_R_BLUE [mm] "BLUE"
  rect 0.75x1 smd mask+0.05: 1(-2.225,0.75) 2(2.225,0.75) 3(-2.225,-0.75) 4(2.225,-0.75)
  silkscreen extent -1.85,-1.6 1.85,1.6, body extent -2.45,-1.6 2.45,1.6, height 2.6

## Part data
B1: library part MCD-00172, "Switch HW SMD blue", Manufacturer=JIUBABA, Manufacturer_Part_Number="C-TS-02H-2.5-B-V-T/R BLUE"
C1 C4 C7 C8 C10 C11 C12 C15 C16 C17 C19 C20 C21 C22 C23 C24 C26 C28 C78 C80 C82: library part MCD-00006, "Capacitor, MLCC, 100nF, 16V, X7R, 10%, 0402, T=0.5mm", Alternate_Manufacturer=MURATA, Alternate_Manufacturer_Part_Number=GCM155R71C104KA55D, Manufacturer=YAGEO, Manufacturer_Part_Number=CC0402KRX7R7BB104, Package=C0402
C2 C13 C14 C27 C30 C32 C35 C36 C37 C41 C45 C46 C47 C48 C50 C53 C54: library part MCD-00095, "Capacitor, MLCC, 1uF, 25V, X5R, 10%, 0402, T=0,5mm", Alternate_Manufacturer=MURATA, Alternate_Manufacturer_Part_Number=GRM155R60J105KE19, Manufacturer_Part_Number=GRM155R61E105KA12, Package=C0402
C3 C5 C6: library part MCD-01823, "Capacitor,MLCC,2.2uF,6V3,X5R,10%,0402,T=0.5", Manufacturer=MURATA, Manufacturer_Part_Number=GRM155R60J225KE95D, Package=C0402
C9 C25: library part MCD-01124, "Capacitor, MLCC, 10uF, 10V, X5R, 10%, 0603, T=0.8mm", Manufacturer=MURATA, Manufacturer_Part_Number=GRM188R61A106KAAL, Package=C0603
C18 C31 C33 C39 C42 C60: library part MCD-00099, "Capacitor, MLCC, 10uF, 10V, X5R, 10%, 0603, T=0,8mm", Manufacturer=MURATA, Manufacturer_Part_Number=GRM188R61A106KE69D, Package=C0603
C29 C34 C38 C40: library part MCD-00100, "Capacitor, MLCC, 22uF, 6V3, X5R, 20%, 0603, T=0,8mm", Manufacturer=MURATA, Manufacturer_Part_Number=GRM188R60J226MEA0J, Package=C0603
C43 C49 C51 C52: library part MCD-01356, "Capacitor, MLCC, 4.7uF, 6V3, X5R, 20%, 0402, T=0,5mm", Alternate_Manufacturer=MURATA, Alternate_Manufacturer_Part_Number=GRM155R60J475ME87, Manufacturer_Part_Number=GRM155R60J475ME47, Package=C0402
C44 C61: library part MCD-00011, "Capacitor, MLCC, 10nF, 16V, X7R, 10%, 0402, T=0.5mm", Manufacturer=YAGEO, Manufacturer_Part_Number=CC0402KRX7R7BB103, Package=C0402
C55 C56 C57: library part MCD-01462, "Capacitor, MLCC, 3.3nF, 16V, X7R, 10%, 0402, T=0.5mm", Manufacturer=YAGEO, Manufacturer_Part_Number=CC0402KRX7R7BB332, Package=C0402
C58 C59: library part MCD-00198, "Capacitor, MLCC, 1nF, 16V, X7R, 10%, 0402, T=0.5mm", Manufacturer=YAGEO, Manufacturer_Part_Number=CC0402KRX7R7BB102, Package=C0402
C79 C81 C83: library part MCD-00012, "Capacitor, MLCC, 2.2uF, 10V, X5R, 10%, 0603, T=0,8mm", Alternate_Manufacturer=KEMET, Alternate_Manufacturer_Part_Number=C0603C225K8PACTU, Manufacturer=YAGEO, Manufacturer_Part_Number=CC0603KRX5R6BB225, Package=C0603
L1 L2 L3 L4: library part MCD-01491, "Inductors 1.0uH 54mOhms3.3A +/-20% 2016", Manufacturer=MURATA, Manufacturer_Part_Number=DFE201612P-1R0M, Package=2016
L5: library part MCD-01134, "IND 4.7uH 20% 80mA 600mhom 0603", Manufacturer=MURATA, Manufacturer_Part_Number=LQM18FN4R7M00D, Package=0603
R1 R31: library part MCD-00120, "Resistor,240R,0402,1%,1/16W", Manufacturer=YAGEO, Manufacturer_Part_Number=RC0402FR-07240RL, Package=R0402
R2: library part MCD-00067, "Resistor,100R,0402,1%,1/16W", Manufacturer=YAGEO, Manufacturer_Part_Number=RC0402FR-07100RL, Package=R0402
R14 R40: library part MCD-00053, "Resistor,10K,0402,1%,1/16W", Manufacturer=YAGEO, Manufacturer_Part_Number=RC0402FR-0710KL, Package=R0402
R37 R38: library part MCD-00068, "Resistor,1K5,0402,1%,1/16W", Manufacturer=YAGEO, Manufacturer_Part_Number=RC0402FR-071K5L, Package=R0402
R39 R41 R42: library part MCD-00052, "Resistor,0R,0402,5%,1/16W", Manufacturer=YAGEO, Manufacturer_Part_Number=RC0402JR-070RL, Package=R0402
R43: library part MCD-00063, "Resistor,47K,0402,1%,1/16W", Manufacturer=YAGEO, Manufacturer_Part_Number=RC0402FR-0747KL, Package=R0402
U1: library part MCD-01144, "MPU TFBGA10x10 secure boot+crypto", Manufacturer=STMICROELECTRONICS, Manufacturer_Part_Number=STM32MP157CAD3
U2: library part MCD-01223, "Memory,LPDDR2,4Gb,128Mbx32,533MHz,1066Mb/s,1V8/1V2,FBGA134", Manufacturer=MICRON, Manufacturer_Part_Number=EDB4432BBBJ-1D-F-R, Package="WFBGA134 10x11.5"
U4: library part MCD-01650, "ST PMIC:  4 step-down + 1 advanced boost SMPS, 6 LDOs, 2 pwr switches, DDR Vref, NVM option 'A' for IO@3.3V", Manufacturer=STMICROELECTRONICS, Manufacturer_Part_Number=STPMIC1APQR, Package="WFQFN 5.0x6.0x0.80mm"
U5: library part MCD-00110, "Memory,e-MMC,4GB,3V3,WFBGA,153pins", Manufacturer=TOSHIBA, Manufacturer_Part_Number=THGBMDG5D1LBAIL

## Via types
v1: diameter 0.4, hole 0.2, Top Layer to Bottom Layer, tented both sides, 276 vias
v2: diameter 0.6, hole 0.3, Top Layer to Bottom Layer, tented both sides, 74 vias
v3: diameter 0.4, hole 0.2, Top Layer to Bottom Layer, 3 vias
v4: diameter 0.4, hole 0.2, Top Layer to Signal Layer 1, tented top, 2 vias

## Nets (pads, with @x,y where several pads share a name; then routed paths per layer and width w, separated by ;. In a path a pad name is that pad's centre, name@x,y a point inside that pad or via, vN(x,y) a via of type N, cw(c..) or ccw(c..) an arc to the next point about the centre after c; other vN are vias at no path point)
3V3: C32.2 C40.2 C78.2 C79.2 L4.2 U4.22 U4.27 U5.E6 U5.F5 U5.J10 U5.K9 | length 48
  Top Layer w0.175: U5.J10@27.15,88.475 U5.K9@27.65,88.975 v1(27.65,89.45) ; U5.E6@29.15,86.475 U5.F5@29.65,86.975 v1(30.075,86.975)
  Top Layer w0.2: 10.825,82.4 11.175,82.75 U4.22@11.375,82.75 ; v1(13.525,80.8) 13.525,81.4 13.725,81.6 U4.27@13.725,82.1
  Top Layer w0.3: C32.2@8.425,80.05 v1(8.425,80.4) 8.425,81 8.825,81.4 9.825,81.4 10.825,82.4
  Top Layer w0.5: C40.2@11.45,77.1 v1(12.125,77.1)
  Top Layer w0.6: C40.2@11.45,77.1 L4.2@11.45,78.3
  Signal Layer 2 w0.3: v1(8.425,80.4) 9.788,79.038 11.725,77.1 v1(12.125,77.1)
  Bottom Layer w0.1: C79.2@26.8,89.575 C79.2@26.925,89.45 ; v1@30,87.05 v1(30.075,86.975)
  Bottom Layer w0.3: v1(13.525,80.8) 12.85,80.125 12.85,77.3 12.65,77.1 v1(12.125,77.1) 12.125,81.4 12.65,81.925 19.761,81.925 21.686,83.85 22.186,83.85 22.45,84.114 22.45,84.486 22.331,84.606 23.006,84.606 23.625,85.225 23.625,86.4 C79.2@26.8,89.575 ; C79.2@26.925,89.45 v1(27.65,89.45) 28.1,89.45 C78.2@30,87.55 v1@30,87.05
5V_VIN: C18.2 C31.2 C33.2 C39.2 C41.2 C51.1 R43.2 U4.8 U4.12 U4.19 U4.24 U4.28 U4.36 U4.37 | length 16.6
  Top Layer w0.09: v1(14.125,80.7) U4.28@14.125,82.1 ; R43.2@19.775,81.725 R43.2@19.9,81.6
  Top Layer w0.1: R43.2@19.775,81.725 C51.1@19.775,82.4
  Top Layer w0.2: C39.2@10.625,80 10.85,80.225 10.85,80.425 11.425,81 11.925,81 12.525,81.6 U4.24@12.525,82.1 ; 10.675,83.95 U4.19@11.375,83.95 ; v1(10.825,87.4) 11.225,87.4 11.625,87 U4.12@12.125,87 ; C31.2@13.725,80 13.75,80.025 14.125,80.4 v1(14.125,80.7) ; U4.8@13.725,87 13.725,88.4 v1(13.525,88.6) 13.525,89.1 C33.2@13.725,89.3 ; U4.36@17.275,83.15 17.674,83.15 18.099,82.725 18.35,82.725 18.675,82.4 v1(19.125,82.4) C51.1@19.775,82.4 C51.1@19.8,82.4 ; U4.37@17.275,83.55 17.9,83.55 v1(18.125,83.325)
  Top Layer w0.3: C41.2@8.975,83.5 9.525,83.5 9.975,83.95 v1(10,83.95) 10.675,83.95
  other v1: 10.425,80.6
DDR_A0: U1.G18 U2.P3 | length 28
  Top Layer w0.09: U1.G18@34.46,69.58 34.465,69.585 34.705,69.825 35.2,69.825
  Top Layer w0.12: 35.2,69.825 35.5,69.525 v1(36.25,69.525) ; v1@51.905,70.925 v1(51.925,70.925) 51.975,70.925 U2.P3@52.3,71.25
  Bottom Layer w0.12: v1(36.25,69.525) 36.475,69.75 36.475,72.006 36.769,72.3 36.9,72.3 37.05,72.15 37.05,70.8 37.35,70.5 38.525,70.5 38.73,70.705 38.73,72.7 38.425,73.005 38.425,73.6 39.08,74.255 48.67,74.255 49.65,73.275 49.65,72.075 50.135,71.59 51.24,71.59 v1@51.905,70.925
DDR_A1: U1.M19 U2.N3 | length 28.5
  Top Layer w0.12: U1.M19@34.975,67.075 37.775,67.075 38.8,68.1 v1(38.8,68.25) ; v1(51.825,69.875) 51.825,70.125 U2.N3@52.3,70.6
  Bottom Layer w0.12: v1(38.8,68.25) 39.225,68.675 40.65,68.675 40.8,68.825 40.8,69 40.6,69.2 39.875,69.2 39.725,69.35 39.725,69.6 39.875,69.75 41.2,69.75 42.23,70.78 42.23,71.505 42.725,72 43.35,72 43.45,72.1 43.45,72.425 43.35,72.525 42.225,72.525 42.075,72.675 42.075,72.85 42.22,72.995 47.85,72.995 48.435,72.41 48.435,70.59 48.75,70.275 51.025,70.275 51.28,70.02 51.68,70.02 v1(51.825,69.875)
DDR_A2: U1.F17 U2.M3 | length 27.5
  Top Layer w0.09: U1.F17@33.96,70.08 33.965,70.085 34.205,70.325 35.071,70.325 35.096,70.3 v1(35.95,70.3)
  Top Layer w0.12: U2.M3@52.3,69.95 52.335,69.95 52.625,70.24 v1(52.625,70.925)
  Bottom Layer w0.12: v1(35.95,70.3) 35.95,72.075 36.595,72.72 37.074,72.72 37.475,72.319 37.475,71.825 37.675,71.625 38.1,71.625 38.31,71.835 38.31,72.495 38.005,72.8 38.005,73.774 38.428,74.197 ; 38.425,74.2 38.9,74.675 48.9,74.675 50,73.575 50,72.8 50.935,71.865 51.685,71.865 v1(52.625,70.925)
DDR_A3: U1.F19 U2.M2 | length 28.2
  Top Layer w0.09: U1.F19@34.99,70.1 34.995,70.095 35.015,70.075 35.525,70.075 35.613,69.988
  Top Layer w0.12: 35.613,69.988 35.7,69.9 36.1,69.9 36.275,70.075 37.05,70.075 v1(37.6,69.525) ; U2.M2@52.95,69.95 v1(53.275,70.275)
  Bottom Layer w0.12: v1(37.6,69.525) 37.775,69.35 37.775,68.975 37.932,68.818 38.593,68.818 39.305,69.53 39.305,69.774 39.806,70.275 40.85,70.275 41.025,70.45 41.025,70.725 40.85,70.9 40.225,70.9 40,71.125 40,71.85 40.35,72.2 40.6,72.2 41.1,71.7 41.5,71.7 41.625,71.825 41.625,73.175 41.865,73.415 48.024,73.415 48.83,72.609 ; 48.855,72.609 48.855,71.25 49.355,70.75 49.55,70.75 49.75,70.55 51.135,70.55 51.39,70.295 52.125,70.295 52.338,70.082 ; 52.285,70.145 52.343,70.087 52.343,69.88 52.468,69.755 52.755,69.755 v1(53.275,70.275) v1@53.27,70.28
DDR_A4: U1.R17 U2.M1 | length 28.4
  Top Layer w0.09: v1(33.55,65) 33.975,65.425 U1.R17@33.975,65.575
  Top Layer w0.12: U2.M1@53.6,69.95 v1(53.925,69.625) v1@53.95,69.6
  Bottom Layer w0.12: v1(33.55,65) 34.875,63.675 35.975,63.675 37.51,62.14 49.325,62.14 50.41,63.225 51.172,63.225 51.487,63.54 51.822,63.54 52.092,63.81 52.378,63.81 53.925,65.357 v1(53.925,69.625)
DDR_A5: U1.1C9 U2.G2 | length 27.1
  Top Layer w0.09: U1.1C9@33.075,69.375 33.225,69.225 v1(33.55,69.225)
  Top Layer w0.12: U2.G2@52.95,66.695 53.273,66.373 v1@53.275,66.37
  Bottom Layer w0.12: v1(33.55,69.225) 33.642,69.225 34.192,69.775 34.675,69.775 35.025,69.425 35.3,69.425 36.103,68.622 36.446,68.622 36.72,68.349 36.72,67.87 36.525,67.675 36.525,67.225 37.405,66.345 37.405,65.67 37.57,65.505 38.505,65.505 39.35,66.35 40.405,66.35 40.705,66.05 40.705,65.226 41.276,64.655 41.775,64.655 42.125,64.305 43.545,64.305 44.03,63.82 46.945,63.82 47.275,64.15 48.35,64.15 49.535,65.335 49.852,65.335 50.012,65.175 51.263,65.175 51.583,65.495 52.395,65.495 v1(53.275,66.375)
DDR_A6: U1.1G9 U2.F2 | length 27.3
  Top Layer w0.09: U1.1G9@33.125,66.725 33.125,66.775 v1(33.375,67.025)
  Top Layer w0.12: U2.F2@52.95,66.05 v1@53.26,65.74
  Bottom Layer w0.12: v1(33.375,67.025) 34.5,67.025 34.675,67.2 35.355,67.2 35.675,66.88 35.675,66.625 35.525,66.475 34.975,66.475 34.85,66.35 34.85,64.294 35.049,64.095 36.511,64.095 38.046,62.56 49.151,62.56 50.236,63.645 50.998,63.645 51.313,63.96 51.648,63.96 51.918,64.23 52.289,64.23 53.275,65.216 v1(53.275,65.725)
DDR_A7: U1.1A9 U2.F3 | length 26.6
  Top Layer w0.09: U1.1A9@33.075,70.675 33.5,70.675 v1(33.55,70.725)
  Top Layer w0.12: U2.F3@52.34,66.09 U2.F3@52.3,66.05 v1(52.625,66.375)
  Bottom Layer w0.12: v1(33.55,70.725) 33.575,70.75 34.425,70.75 36.07,69.105 36.695,69.105 37.14,68.66 37.14,67.46 37.825,66.775 37.825,66.075 37.975,65.925 38.225,65.925 38.425,66.125 38.425,66.625 38.575,66.775 40.85,66.775 41.125,66.5 41.125,65.4 41.45,65.075 42.125,65.075 42.475,64.725 44.8,64.725 45.285,64.24 46.215,64.24 46.9,64.925 48.531,64.925 49.361,65.755 50.026,65.755 50.251,65.53 51.024,65.53 51.409,65.915 52.165,65.915 v1(52.625,66.375)
DDR_A8: U1.T17 U2.E3 | length 26.1
  Top Layer w0.09: U1.T17@33.975,65.075 34.222,65.322 34.222,65.678 34.364,65.82 34.725,65.82 34.8,65.895 34.8,65.9 34.825,65.925 35.25,65.925
  Top Layer w0.12: 35.25,65.925 35.375,65.925 35.675,66.225 v1(36.525,66.225) ; v1(51.975,65.075) U2.E3@52.3,65.4
  Bottom Layer w0.12: v1(36.525,66.225) 36.525,65.269 38.219,63.575 38.875,63.575 39.122,63.822 39.122,65.528 39.524,65.93 40.02,65.93 40.285,65.665 40.285,63.665 40.55,63.4 48.803,63.4 49.239,63.836 49.239,64.445 49.594,64.8 51.3,64.8 51.575,65.075 v1(51.975,65.075)
DDR_A9: U1.E18 U2.E2 | length 28.5
  Top Layer w0.09: U1.E18@34.46,70.58 34.475,70.58 35.305,70.58 35.425,70.7 36.24,70.7 36.365,70.575
  Top Layer w0.12: v1(36.3,68.175) 37.225,69.1 37.825,69.1 37.975,69.25 37.975,69.825 37.35,70.45 36.49,70.45 36.365,70.575 ; v1(52.625,65.075) U2.E2@52.95,65.4
  Bottom Layer w0.12: v1(36.3,68.175) 36.105,67.98 36.105,65.095 38.22,62.98 48.977,62.98 50.062,64.065 50.824,64.065 51.035,64.276 51.035,64.29 51.125,64.38 51.474,64.38 51.744,64.65 52.2,64.65 v1(52.625,65.075)
DDR_CKE: R14.2 U1.P17 U2.K1 | length 31.6
  Top Layer w0.09: U1.P17@33.95,66.08 33.975,66.08 34.116,66.08 34.366,66.33 34.595,66.33 34.765,66.16 35.075,66.16
  Top Layer w0.12: 35.075,66.16 35.615,66.7 37.875,66.7 39.4,68.225 v1(39.4,68.25) ; v1(53.3,68.95) U2.K1@53.6,68.65 53.9,68.95 57.025,68.95 R14.2@57.05,68.975 R14.2@57.1,69.025
  Bottom Layer w0.12: v1(39.4,68.25) 41.275,68.25 41.5,68.475 41.5,69.325 41.825,69.65 42.475,69.65 42.65,69.825 42.65,70.25 42.875,70.475 42.875,70.8 42.65,71.025 42.65,71.3 42.925,71.575 44.5,71.575 44.7,71.775 44.7,72.425 44.85,72.575 45.075,72.575 45.525,72.125 45.65,72.125 46.1,72.575 47.546,72.575 47.71,72.411 47.71,71.636 47.835,71.511 47.835,70.015 47.995,69.855 48.705,69.855 ; 48.725,69.855 48.705,69.855 ; v1(53.3,68.95) 52.915,69.335 52.294,69.335 52.169,69.46 51.465,69.46 50.9,70.025 48.875,70.025 48.705,69.855
DDR_CLK_N: R2.2 U1.K18 U2.H3 | length 29.3
  Top Layer w0.09: U1.K18@34.475,68.075 34.625,68.075 34.665,68.035 34.935,67.766 ; 34.935,67.765 35.075,67.625
  Top Layer w0.1: 35.08,67.63 37.548,67.63 37.775,67.857 37.775,68.063 37.625,68.213 v1(37.625,68.25) ; U2.H3@52.3,67.35 v1(52.625,67.675)
  Bottom Layer w0.1: v1(37.625,68.25) 37.775,68.1 37.775,67.7 38.155,67.32 41.18,67.32 41.57,66.93 41.57,66.655 42.03,66.195 42.445,66.195 42.955,66.705 42.955,67.245 42.2,68 42.2,68.55 42.4,68.75 43.375,68.75 43.595,68.53 43.595,67.055 43.955,66.695 44.62,66.695 44.925,67 44.925,68.525 45.1,68.7 45.325,68.7 45.47,68.555 45.47,68.005 45.89,67.585 46.69,67.585 46.875,67.77 48.95,67.77 49.2,67.52 49.2,67.51 49.365,67.345 50.295,67.345 50.395,67.445 51.67,67.445 52.11,67.885 52.415,67.885 v1(52.625,67.675) R2.2@53.165,67.675
DDR_CLK_P: R2.1 U1.L17 U2.J3 | length 29.9
  Top Layer w0.09: U1.L17@33.97,67.58 34.22,67.83 34.559,67.83 34.574,67.815 ; 34.574,67.815 34.715,67.674 34.984,67.405 35.02,67.405 35.025,67.4
  Top Layer w0.1: 35.025,67.4 37.643,67.4 38.005,67.762 38.005,68.063 38.125,68.183 v1(38.125,68.25) ; U2.J3@52.3,68 v1(52.625,68.325)
  Bottom Layer w0.1: v1(38.125,68.25) 38.005,68.13 38.005,67.795 38.25,67.55 41.275,67.55 41.8,67.025 41.8,66.75 42.125,66.425 42.35,66.425 42.725,66.8 42.725,67.15 41.97,67.905 41.97,68.645 42.305,68.98 43.47,68.98 43.825,68.625 43.825,67.15 44.05,66.925 44.525,66.925 44.695,67.095 44.695,68.62 45.005,68.93 45.42,68.93 45.7,68.65 45.7,68.1 45.985,67.815 46.585,67.815 46.77,68 49.065,68 49.49,67.575 50.2,67.575 50.3,67.675 51.575,67.675 52.015,68.115 52.375,68.115 52.585,68.325 v1(52.625,68.325) R2.1@53.245,68.325
DDR_CSN: U1.J17 U2.L1 | length 30.1
  Top Layer w0.09: U1.J17@33.97,68.58 U1.J17@33.975,68.575 34.22,68.82 34.633,68.82 34.75,68.937
  Top Layer w0.12: 34.75,68.937 36.312,68.937 v1(36.9,69.525) ; v1(53.3,69.6) U2.L1@53.6,69.3
  Bottom Layer w0.12: v1(36.9,69.525) 37.4,70.025 37.85,70.025 38.275,69.6 38.537,69.6 39.5,70.563 39.5,70.95 39.15,71.3 39.15,71.525 39.5,71.875 39.5,72.075 39.15,72.425 39.15,72.9 39.4,73.15 39.4,73.5 39.7,73.8 40.063,73.8 40.2,73.663 40.2,72.895 40.475,72.62 41.07,72.62 41.205,72.755 41.205,73.605 41.435,73.835 48.223,73.835 49.23,72.828 ; 49.243,72.841 49.25,72.834 49.25,71.856 49.815,71.285 50.836,71.285 51.556,70.565 52.915,70.565 53.063,70.713 53.463,70.713 53.75,70.425 53.75,70.05 v1(53.3,69.6)
DDR_DQ0: U1.A17 U2.N8 | length 23.4
  Top Layer w0.12: U1.A17@33.975,72.575 33.975,74.325 34.75,75.1 35.175,75.1 35.49,75.415 35.76,75.415 36.075,75.1 37.425,75.1 37.525,75.2 37.525,75.5 37.65,75.625 38.025,75.625 38.15,75.5 38.15,75.225 38.275,75.1 38.7,75.1 38.825,75.225 38.825,75.775 39.025,75.975 45.975,75.975 46.675,75.275 46.675,74.369 47.444,73.6 48.675,73.6 49.375,72.9 49.375,70.925 U2.N8@49.05,70.6
DDR_DQ1: U1.A18 U2.M8 | length 23.4
  Top Layer w0.09: U1.A18@34.47,72.58 34.47,72.995 34.75,73.275
  Top Layer w0.12: 34.75,73.275 34.875,73.4 34.875,73.625 35.425,74.175 41.675,74.175 41.8,74.3 41.8,74.525 41.675,74.65 40.575,74.65 40.45,74.775 40.45,74.975 40.575,75.1 45.475,75.1 45.825,74.75 45.825,74 46.675,73.15 46.675,71.375 47.125,70.925 47.875,70.925 48.075,70.725 48.075,69.8 48.25,69.625 48.725,69.625 U2.M8@49.05,69.95
DDR_DQ2: U1.C18 U2.M7 | length 22.4
  Top Layer w0.09: U1.C18@34.47,71.58 U1.C18@34.475,71.575 34.72,71.33 36.315,71.33
  Top Layer w0.12: 36.329,71.346 36.858,71.875 39.794,71.875 40.034,71.634 40.334,71.634 40.535,71.835 41.515,71.835 41.575,71.775 41.575,71.55 41.5,71.475 40.95,71.475 40.85,71.375 40.85,71.206 40.956,71.1 41.5,71.1 41.575,71.025 41.575,70.725 41.5,70.65 41.075,70.65 41,70.575 41,70.3 41.825,69.475 45,69.475 45.15,69.625 45.15,70.225 45.275,70.35 45.5,70.35 45.625,70.225 45.625,69.575 45.725,69.475 46.375,69.475 46.875,68.975 47.08,68.77 48.695,68.77 48.915,68.99 49.178,68.99 49.36,69.172 49.36,69.41 49.7,69.75 U2.M7@49.7,69.95
DDR_DQ3: U1.B16 U2.M9 | length 22.8
  Top Layer w0.09: U1.B16@33.47,72.08 33.71,72.32 34.076,72.32 34.225,72.465 34.225,73.2 34.3,73.275
  Top Layer w0.12: 34.3,73.275 34.45,73.425 34.45,73.95 35.15,74.65 39.775,74.65 39.875,74.75 39.875,74.975 39.6,75.25 39.6,75.425 39.725,75.55 45.75,75.55 46.25,75.05 46.25,74.2 47.575,72.875 48.55,72.875 48.725,72.7 48.725,70.275 U2.M9@48.4,69.95
DDR_DQ4: U1.D18 U2.M6 | length 24.2
  Top Layer w0.09: U1.D18@34.47,71.08 34.475,71.08 34.614,71.08 34.864,70.83 35.155,70.83 35.25,70.925 36.375,70.925 36.475,70.825
  Top Layer w0.12: 36.475,70.825 37.05,70.825 37.15,70.925 37.375,70.925 38.375,69.925 38.375,69.175 38.125,68.925 38.125,68.75 38.225,68.65 40.3,68.65 40.45,68.8 40.45,68.975 40.325,69.1 38.875,69.1 38.775,69.2 38.775,69.425 38.875,69.525 40.587,69.525 40.9,69.212 40.9,68.725 41.025,68.6 42.475,68.6 42.675,68.8 46.375,68.8 46.85,68.325 49.157,68.325 49.442,68.61 49.735,68.61 50.025,68.9 50.025,69.85 50.125,69.95 U2.M6@50.35,69.95
DDR_DQ5: U1.D19 U2.L7 | length 23.6
  Top Layer w0.09: U1.D19@34.97,71.08 34.99,71.1 36.75,71.1
  Top Layer w0.12: 36.75,71.1 36.85,71.2 36.85,71.425 36.925,71.5 37.075,71.5 37.225,71.35 37.5,71.35 37.625,71.475 37.8,71.475 37.9,71.375 37.9,70.875 38.075,70.7 38.225,70.7 38.325,70.8 38.325,71.35 38.45,71.475 38.955,71.475 39.05,71.38 39.05,71.188 38.825,70.962 38.825,70.85 38.9,70.775 39.225,70.775 39.425,70.975 39.525,70.975 39.725,70.775 39.925,70.775 39.996,70.846 39.996,71.136 40.075,71.214 40.248,71.214 40.575,70.887 40.575,70.475 40.475,70.375 38.9,70.375 38.795,70.27 38.795,70.05 38.895,69.95 40.756,69.95 41.32,69.386 41.32,69.125 41.425,69.02 41.925,69.02 ; 41.925,69.025 42.27,69.025 42.395,69.15 46.375,69.15 46.975,68.55 48.875,68.55 49.095,68.77 49.27,68.77 49.475,68.975 49.6,68.975 49.7,69.075 U2.L7@49.7,69.3
DDR_DQ6: U1.C19 U2.L8 | length 23.5
  Top Layer w0.09: U1.C19@34.96,71.58 34.975,71.58 35.98,71.58
  Top Layer w0.12: 35.982,71.593 36.644,72.255 41.87,72.255 41.995,72.13 41.995,70.551 41.772,70.328 41.772,70.122 41.999,69.895 42.375,69.895 42.5,70.02 42.5,71.525 42.6,71.625 42.8,71.625 42.925,71.5 42.925,69.912 43.062,69.775 43.2,69.775 43.325,69.9 43.325,70.525 43.425,70.625 43.6,70.625 43.675,70.55 43.675,69.95 43.85,69.775 44.625,69.775 44.75,69.9 44.75,70.55 44.875,70.675 45.825,70.675 45.925,70.575 45.925,70.35 46.025,70.25 46.025,69.9 46.15,69.775 46.425,69.775 47,69.2 47.21,68.99 48.528,68.99 48.838,69.3 U2.L8@49.05,69.3
DDR_DQ7: U1.B17 U2.L9 | length 23.6
  Top Layer w0.09: U1.B17@33.97,72.08 33.975,72.08 34.115,72.08 34.365,72.33 34.58,72.33 34.73,72.48 34.73,72.843 35.112,73.225
  Top Layer w0.12: 35.112,73.225 35.612,73.725 42.55,73.725 42.675,73.85 42.675,74.5 42.8,74.625 44.8,74.625 44.95,74.475 44.95,74.275 44.85,74.175 43.225,74.175 43.15,74.1 43.15,73.8 43.225,73.725 45.5,73.725 46.225,73 46.225,70.525 46.975,69.775 47.475,69.775 47.625,69.625 47.875,69.625 48.2,69.3 U2.L9@48.4,69.3
DDR_DQ8: U1.R18 U2.F6 | length 24.5
  Top Layer w0.09: U1.R18@34.475,65.575 34.725,65.325 35.25,65.325 35.5,65.075 35.825,65.075 36.05,65.3
  Top Layer w0.12: 36.05,65.3 36.325,65.575 36.519,65.575 37.019,65.075 37.55,65.075 37.675,65.2 37.675,65.45 37.575,65.55 37.225,65.55 37.025,65.75 37.025,66.155 37.15,66.28 37.35,66.28 37.605,66.025 37.794,66.025 38.097,66.328 38.284,66.328 38.613,66 38.75,66 38.9,66.15 38.9,66.925 39,67.025 39.275,67.025 39.375,66.925 39.375,66.15 39.525,66 39.675,66 39.825,66.15 39.825,67.975 40.025,68.175 40.75,68.175 41.035,67.89 41.415,67.89 41.705,68.18 42.07,68.18 42.475,67.775 45.35,67.775 45.6,67.525 45.75,67.525 46,67.775 46.175,67.775 46.26,67.69 49.46,67.69 50.04,67.11 50.04,66.36 U2.F6@50.35,66.05
DDR_DQ9: U1.U19 U2.G8 | length 24.4
  Top Layer w0.09: U1.U19@34.975,64.575 35.15,64.575 35.25,64.475 35.95,64.475 36.275,64.15
  Top Layer w0.12: 36.275,64.15 36.625,63.8 42.5,63.8 42.7,64 42.7,64.225 42.575,64.35 41.325,64.35 41.225,64.45 41.225,64.825 41.3,64.9 41.95,64.9 42.075,65.025 42.075,66.55 42.2,66.675 42.475,66.675 42.575,66.575 42.575,65.85 42.7,65.725 43.575,65.725 43.7,65.85 43.7,66.575 43.85,66.725 44.6,66.725 44.775,66.55 44.775,65.15 44.95,64.975 45.6,64.975 45.8,65.175 45.8,65.425 46.225,65.85 46.225,66.275 46.98,67.03 48.72,67.03 U2.G8@49.05,66.7
DDR_DQ10: U1.T19 U2.G7 | length 24.2
  Top Layer w0.09: U1.T19@34.97,65.08 34.975,65.08 35.2,65.08 35.405,64.875 36.625,64.875 36.737,64.762
  Top Layer w0.12: 36.737,64.762 36.85,64.65 40.125,64.65 40.25,64.775 40.25,65 40.125,65.125 38.225,65.125 38.125,65.225 38.125,65.425 38.25,65.55 40.075,65.55 40.25,65.725 40.25,66.45 40.35,66.55 41.075,66.55 41.2,66.675 41.2,66.875 41.075,67 40.35,67 40.25,67.1 40.25,67.375 40.345,67.47 45.08,67.47 45.65,66.9 45.85,66.9 46.42,67.47 49.255,67.47 49.7,67.025 U2.G7@49.7,66.7
DDR_DQ11: U1.W18 U2.G9 | length 24.1
  Top Layer w0.12: U1.W18@34.475,63.575 34.475,62.807 35.507,61.775 41.425,61.775 41.5,61.7 41.5,61.375 41.425,61.3 39.625,61.3 39.525,61.2 39.525,60.95 39.65,60.825 44.275,60.825 44.875,61.425 44.875,62.331 46.99,64.446 46.99,65.09 47.625,65.725 48.55,65.725 48.725,65.9 48.725,66.375 U2.G9@48.4,66.7
DDR_DQ12: U1.W17 U2.F8 | length 24.2
  Top Layer w0.12: U1.W17@33.975,63.575 33.975,62.119 35.269,60.825 36.775,60.825 37,60.6 37,60.2 37.3,59.9 44.7,59.9 45.363,60.563 45.613,60.563 45.825,60.35 46.075,60.35 46.325,60.6 46.325,60.775 45.85,61.25 45.85,62.075 46.225,62.45 48.875,62.45 49.375,62.95 49.375,65.725 U2.F8@49.05,66.05
DDR_DQ13: U1.T18 U2.F7 | length 24.8
  Top Layer w0.09: U1.T18@34.48,65.07 34.625,65.07 34.87,64.825 35.175,64.825 35.325,64.675 36.35,64.675 36.525,64.5
  Top Layer w0.12: 36.525,64.5 36.8,64.225 40.5,64.225 40.7,64.425 40.7,66.025 40.805,66.13 41.07,66.13 41.175,66.025 41.175,65.425 41.25,65.35 41.55,65.35 41.625,65.425 41.625,66.85 41.875,67.1 42.7,67.1 42.95,66.85 42.95,66.125 43.05,66.025 43.25,66.025 43.35,66.125 43.35,66.95 43.5,67.1 44.9,67.1 45.125,66.875 45.125,65.45 45.25,65.325 45.4,65.325 45.5,65.425 45.5,65.675 45.9,66.075 45.9,66.5 46.65,67.25 48.938,67.25 49.39,66.799 49.39,66.572 49.7,66.262 U2.F7@49.7,66.05
DDR_DQ14: U1.U17 U2.F9 | length 23.7
  Top Layer w0.09: U1.U17@33.97,64.58 U1.U17@33.975,64.575 34.22,64.33 34.22,63.98 34.375,63.825 34.575,63.825 34.725,63.675 34.725,63.075 34.9,62.9
  Top Layer w0.12: 34.9,62.9 35.2,62.6 35.475,62.6 35.825,62.25 43.65,62.25 43.8,62.1 43.8,61.875 43.675,61.75 42.125,61.75 42.025,61.65 42.025,61.4 42.15,61.275 44.075,61.275 44.35,61.55 44.35,62.4 46.57,64.62 46.57,65.601 46.725,65.756 46.725,66.15 46.85,66.275 47.375,66.275 47.475,66.375 48.075,66.375 U2.F9@48.4,66.05
DDR_DQ15: U1.V17 U2.E8 | length 24.5
  Top Layer w0.09: U1.V17@33.97,64.08 33.97,64.075 33.97,63.926 34.225,63.671 34.225,62.463 34.381,62.306
  Top Layer w0.12: 34.381,62.306 35.388,61.3 38.95,61.3 39.05,61.2 39.05,60.925 38.95,60.825 37.625,60.825 37.525,60.725 37.525,60.425 37.625,60.325 44.425,60.325 45.325,61.225 45.325,62.187 46.263,63.125 48.55,63.125 48.725,63.3 48.725,65.075 U2.E8@49.05,65.4
DDR_DQM0: U1.C17 U2.K5 | length 21.2
  Top Layer w0.09: U1.C17@33.97,71.58 34.22,71.83 35.63,71.83
  Top Layer w0.12: 35.635,71.84 36.47,72.675 42.344,72.675 43.575,71.444 v1(43.575,71.1) ; U2.K5@51,68.65 51.175,68.825 v1(51.45,68.825)
  Bottom Layer w0.12: v1(43.575,71.1) 43.875,71.1 45.29,69.685 45.635,69.685 46.91,68.41 49.39,68.41 49.85,67.95 50.925,67.95 51.15,68.175 51.15,68.525 v1(51.45,68.825)
DDR_DQM1: U1.V18 U2.H5 | length 20.2
  Top Layer w0.09: U1.V18@34.475,64.075 34.629,64.075 34.879,63.825 35.1,63.825 35.6,63.325
  Top Layer w0.12: 35.6,63.325 36.2,62.725 44.081,62.725 v1@46.125,64.769 ; U2.H5@51,67.35 v1@51.34,67.01
  Bottom Layer w0.12: v1(46.125,64.8) 46.675,65.35 48.362,65.35 49.187,66.175 50.2,66.175 50.425,65.95 50.85,65.95 51.1,66.2 51.1,66.7 v1(51.4,67)
DDR_DQS0_N: U1.B18 U2.L5 | length 21
  Top Layer w0.1: U1.B18@34.47,72.08 34.475,72.08 34.616,72.08 34.861,72.325 35.2,72.325 36.19,73.315 42.609,73.315 42.849,73.075 45.25,73.075 45.471,72.854 45.471,71.254 v1(45.625,71.1) ; v1(50.675,69.625) U2.L5@51,69.3
  Bottom Layer w0.1: v1(45.625,71.1) 45.471,70.946 45.471,70.554 45.7,70.325 46.425,70.325 46.805,69.945 46.805,69.42 47.175,69.05 48.575,69.05 48.94,69.415 50.465,69.415 v1(50.675,69.625)
DDR_DQS0_P: U1.B19 U2.L6 | length 20.4
  Top Layer w0.1: U1.B19@34.975,72.075 35.29,72.075 36.3,73.085 42.514,73.085 42.754,72.845 45.155,72.845 45.241,72.759 45.241,71.258 v1(45.087,71.104) ; U2.L6@50.35,69.3 v1(50.675,68.975)
  Bottom Layer w0.1: v1(45.087,71.104) 45.241,70.95 45.241,70.459 45.605,70.095 46.33,70.095 46.575,69.85 46.575,69.325 47.08,68.82 48.67,68.82 49.035,69.185 50.465,69.185 v1(50.675,68.975)
DDR_DQS1_N: U1.U18 U2.G5 | length 21.3
  Top Layer w0.1: U1.U18@34.47,64.58 34.475,64.58 34.62,64.58 34.875,64.325 35.079,64.325 35.129,64.275 35.55,64.275 36.45,63.375 43.55,63.375 43.725,63.55 43.725,63.775 43.166,64.334 43.166,65.075 v1(43.012,65.229) ; v1(50.675,67.025) U2.G5@51,66.7
  Bottom Layer w0.1: v1(43.012,65.229) 43.166,65.383 43.166,65.616 43.409,65.859 45.609,65.859 47.12,67.37 48.48,67.37 49.035,66.815 50.465,66.815 v1(50.675,67.025)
